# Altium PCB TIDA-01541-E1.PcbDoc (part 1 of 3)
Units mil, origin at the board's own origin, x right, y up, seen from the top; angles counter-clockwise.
Board outline 6299.21 x 6141.73 mil, 4 copper layers (Top Layer, GND, PWR, Bottom Layer), stack 79.834 mil thick; 369 components, 173 nets, 884 pads, 265 vias.
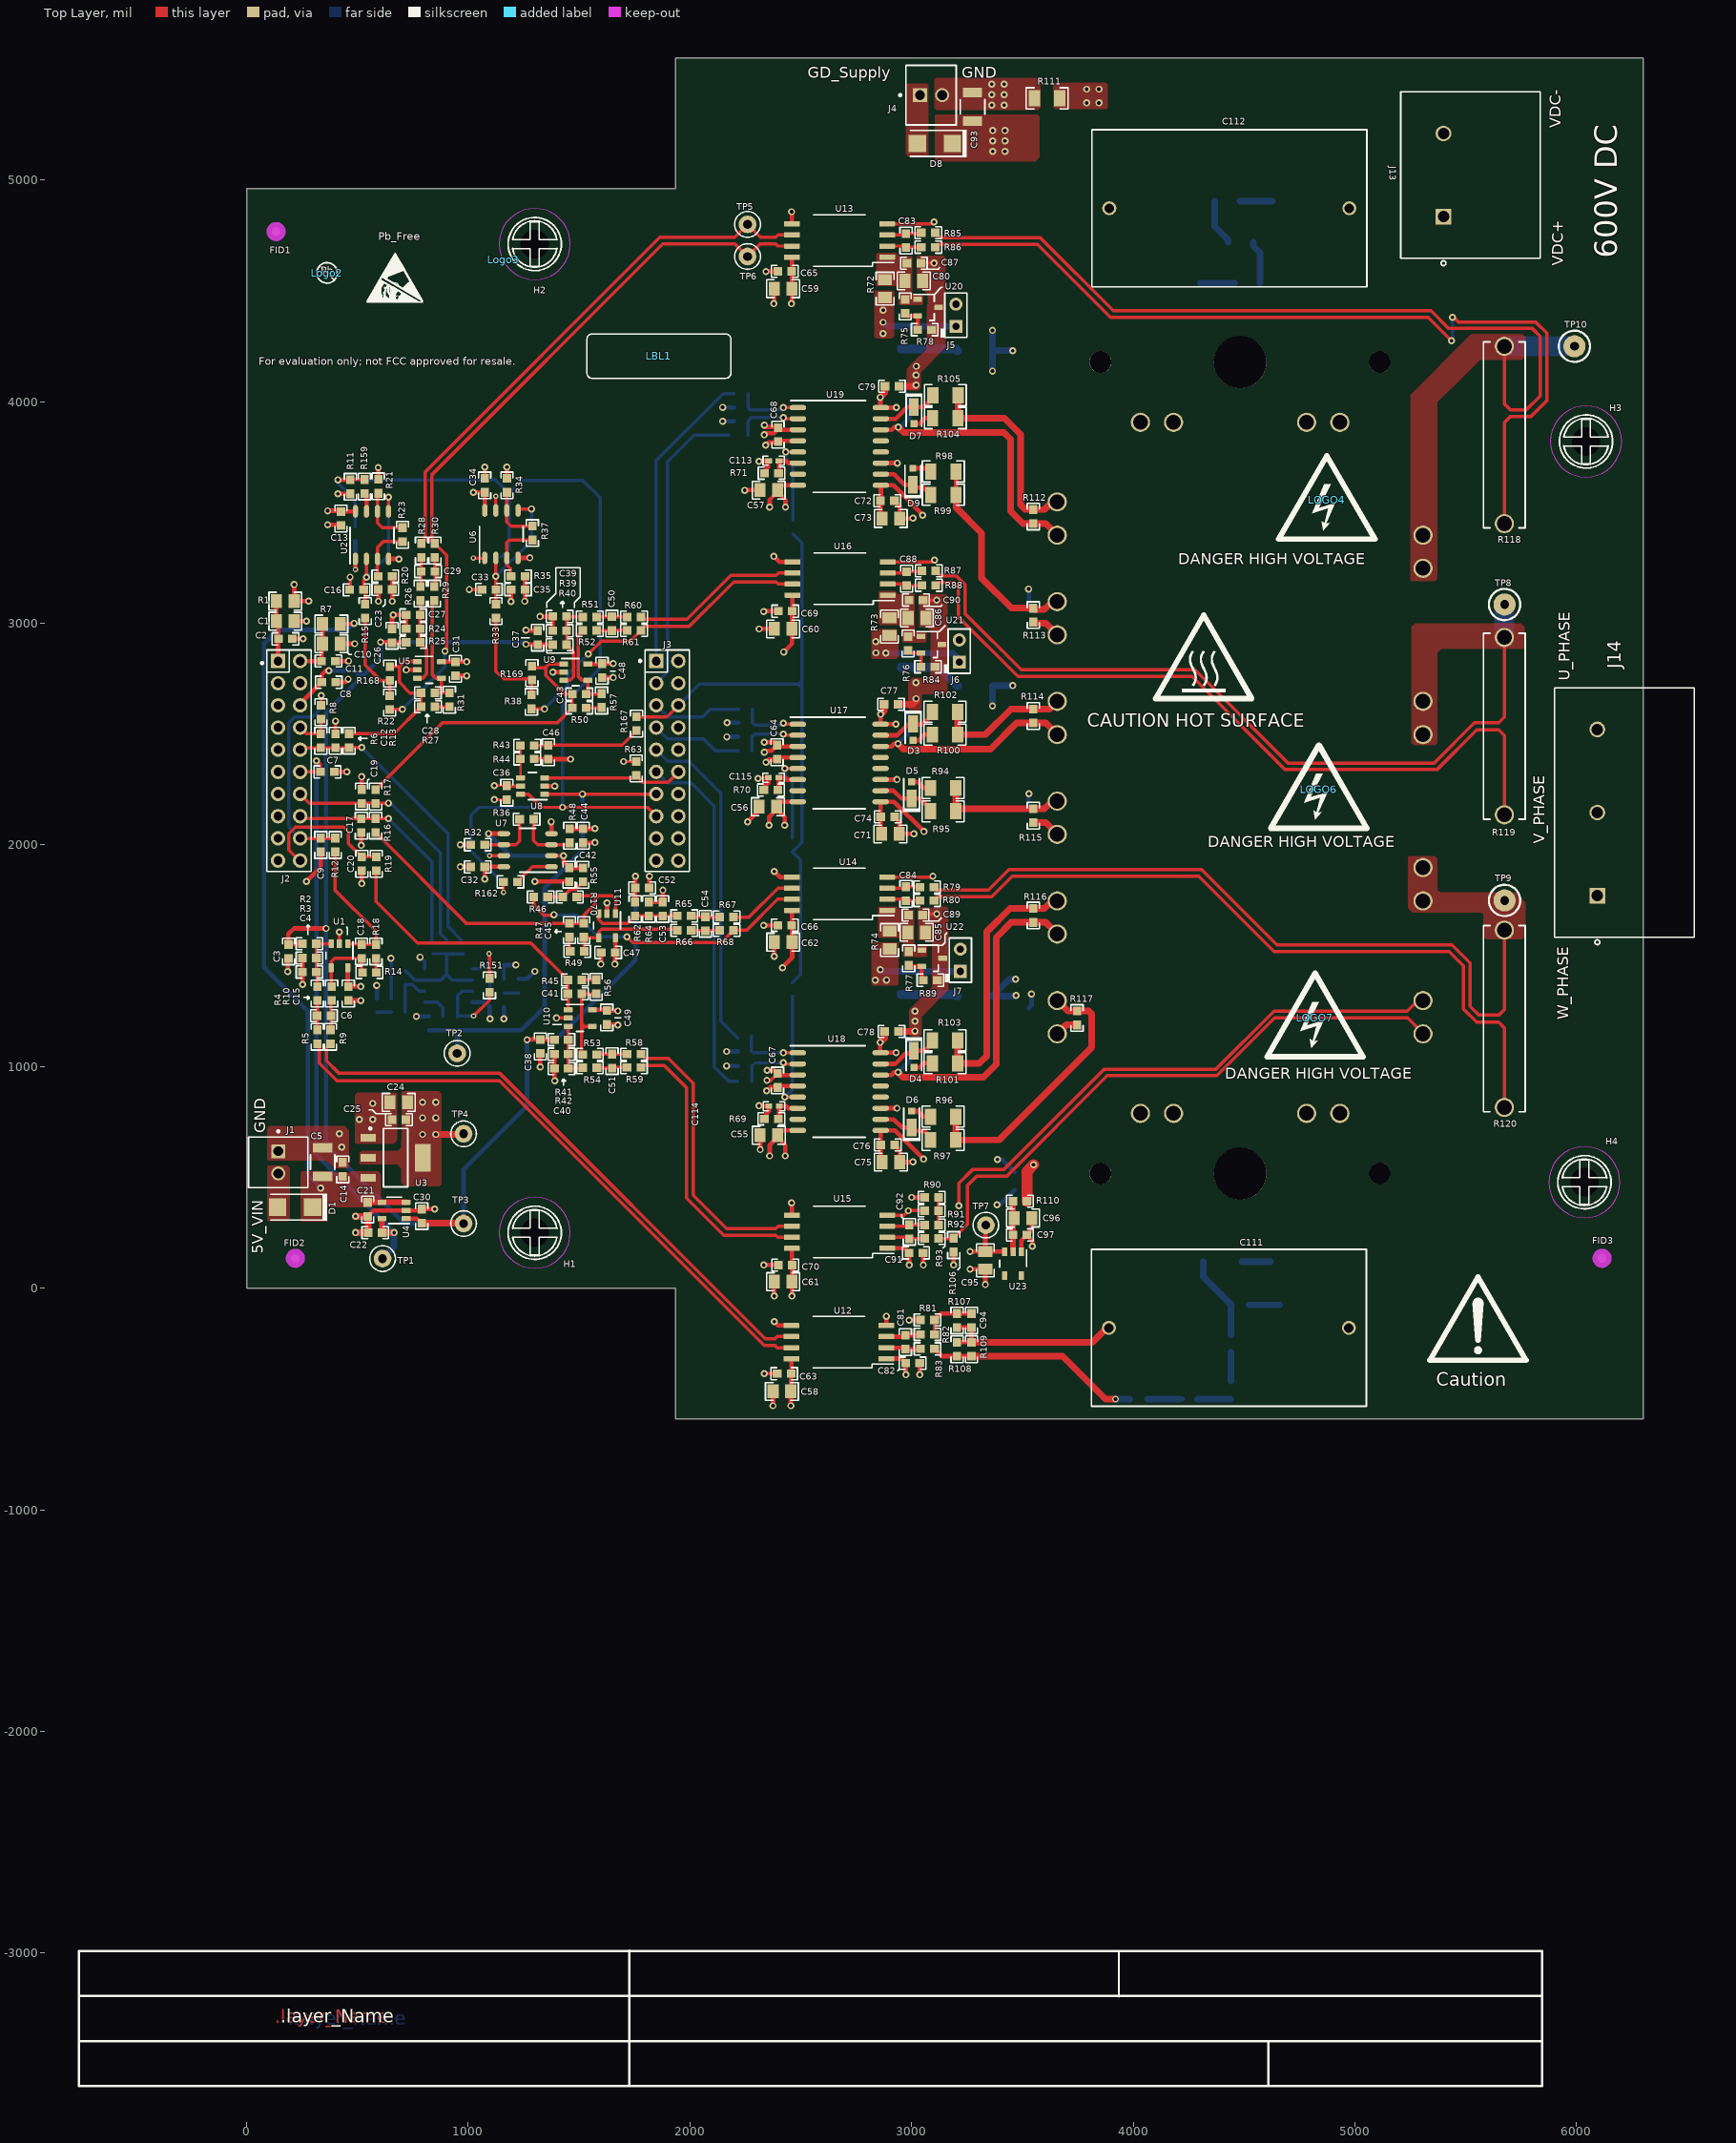
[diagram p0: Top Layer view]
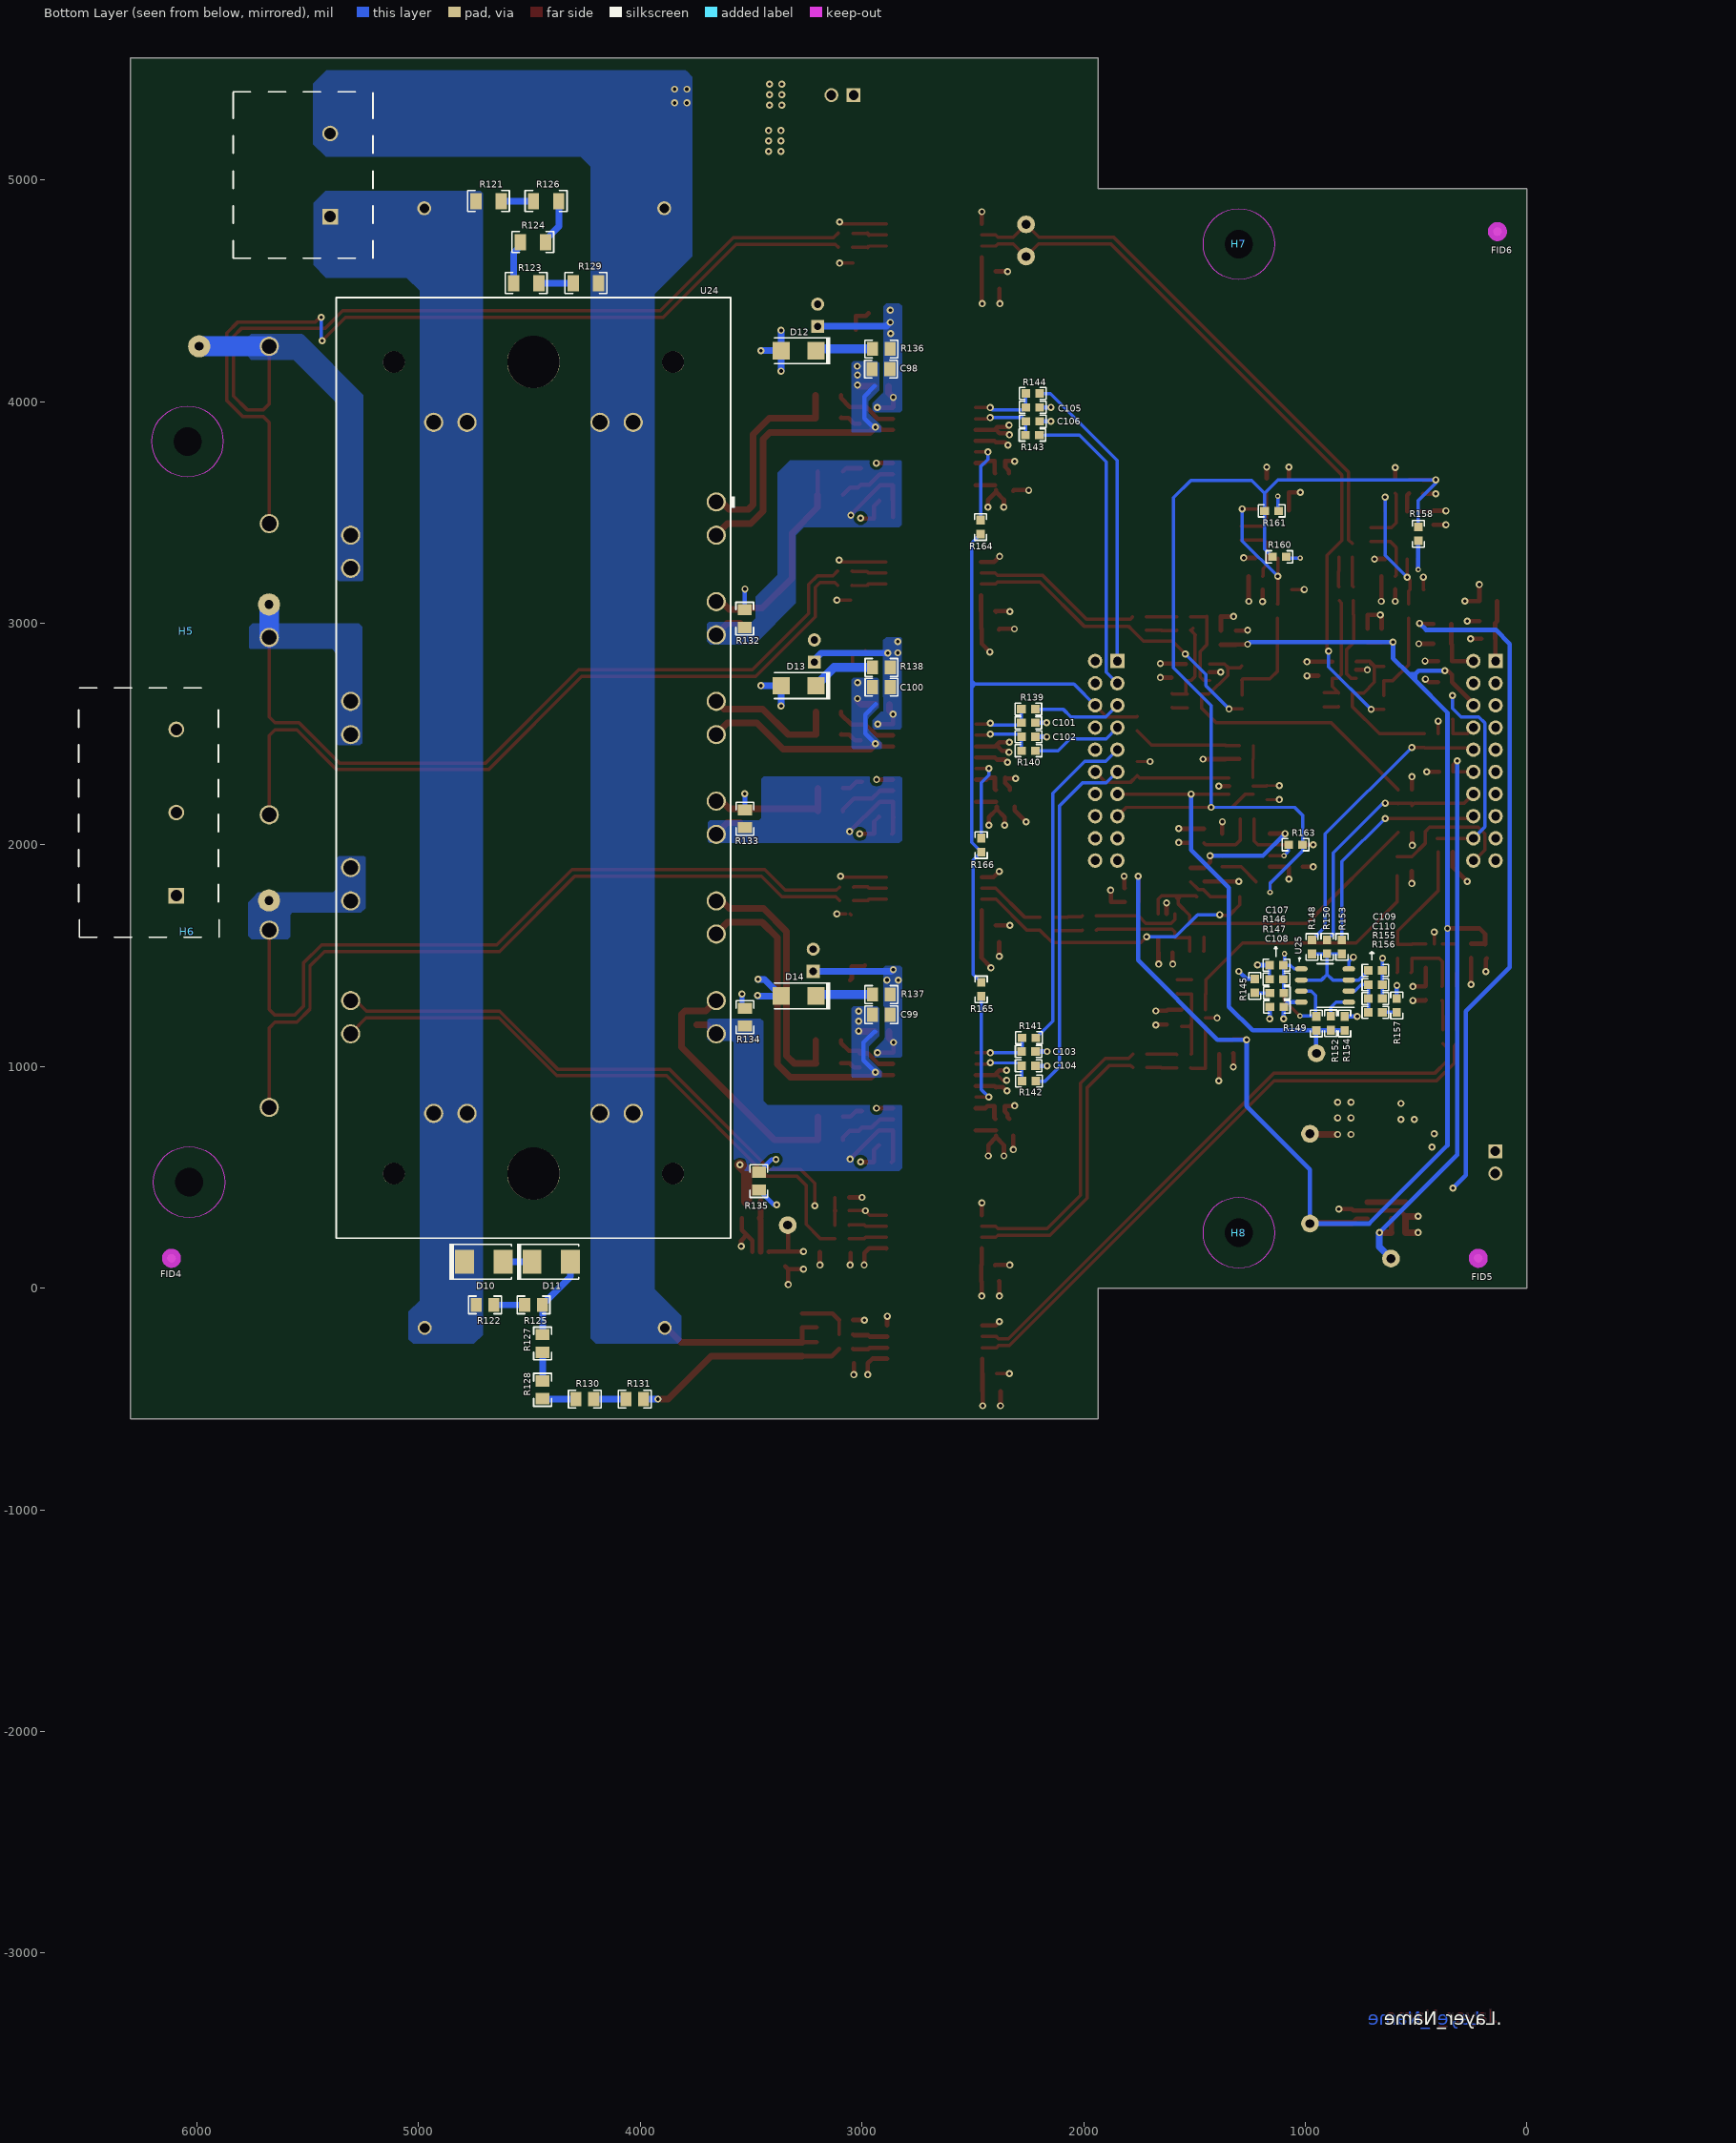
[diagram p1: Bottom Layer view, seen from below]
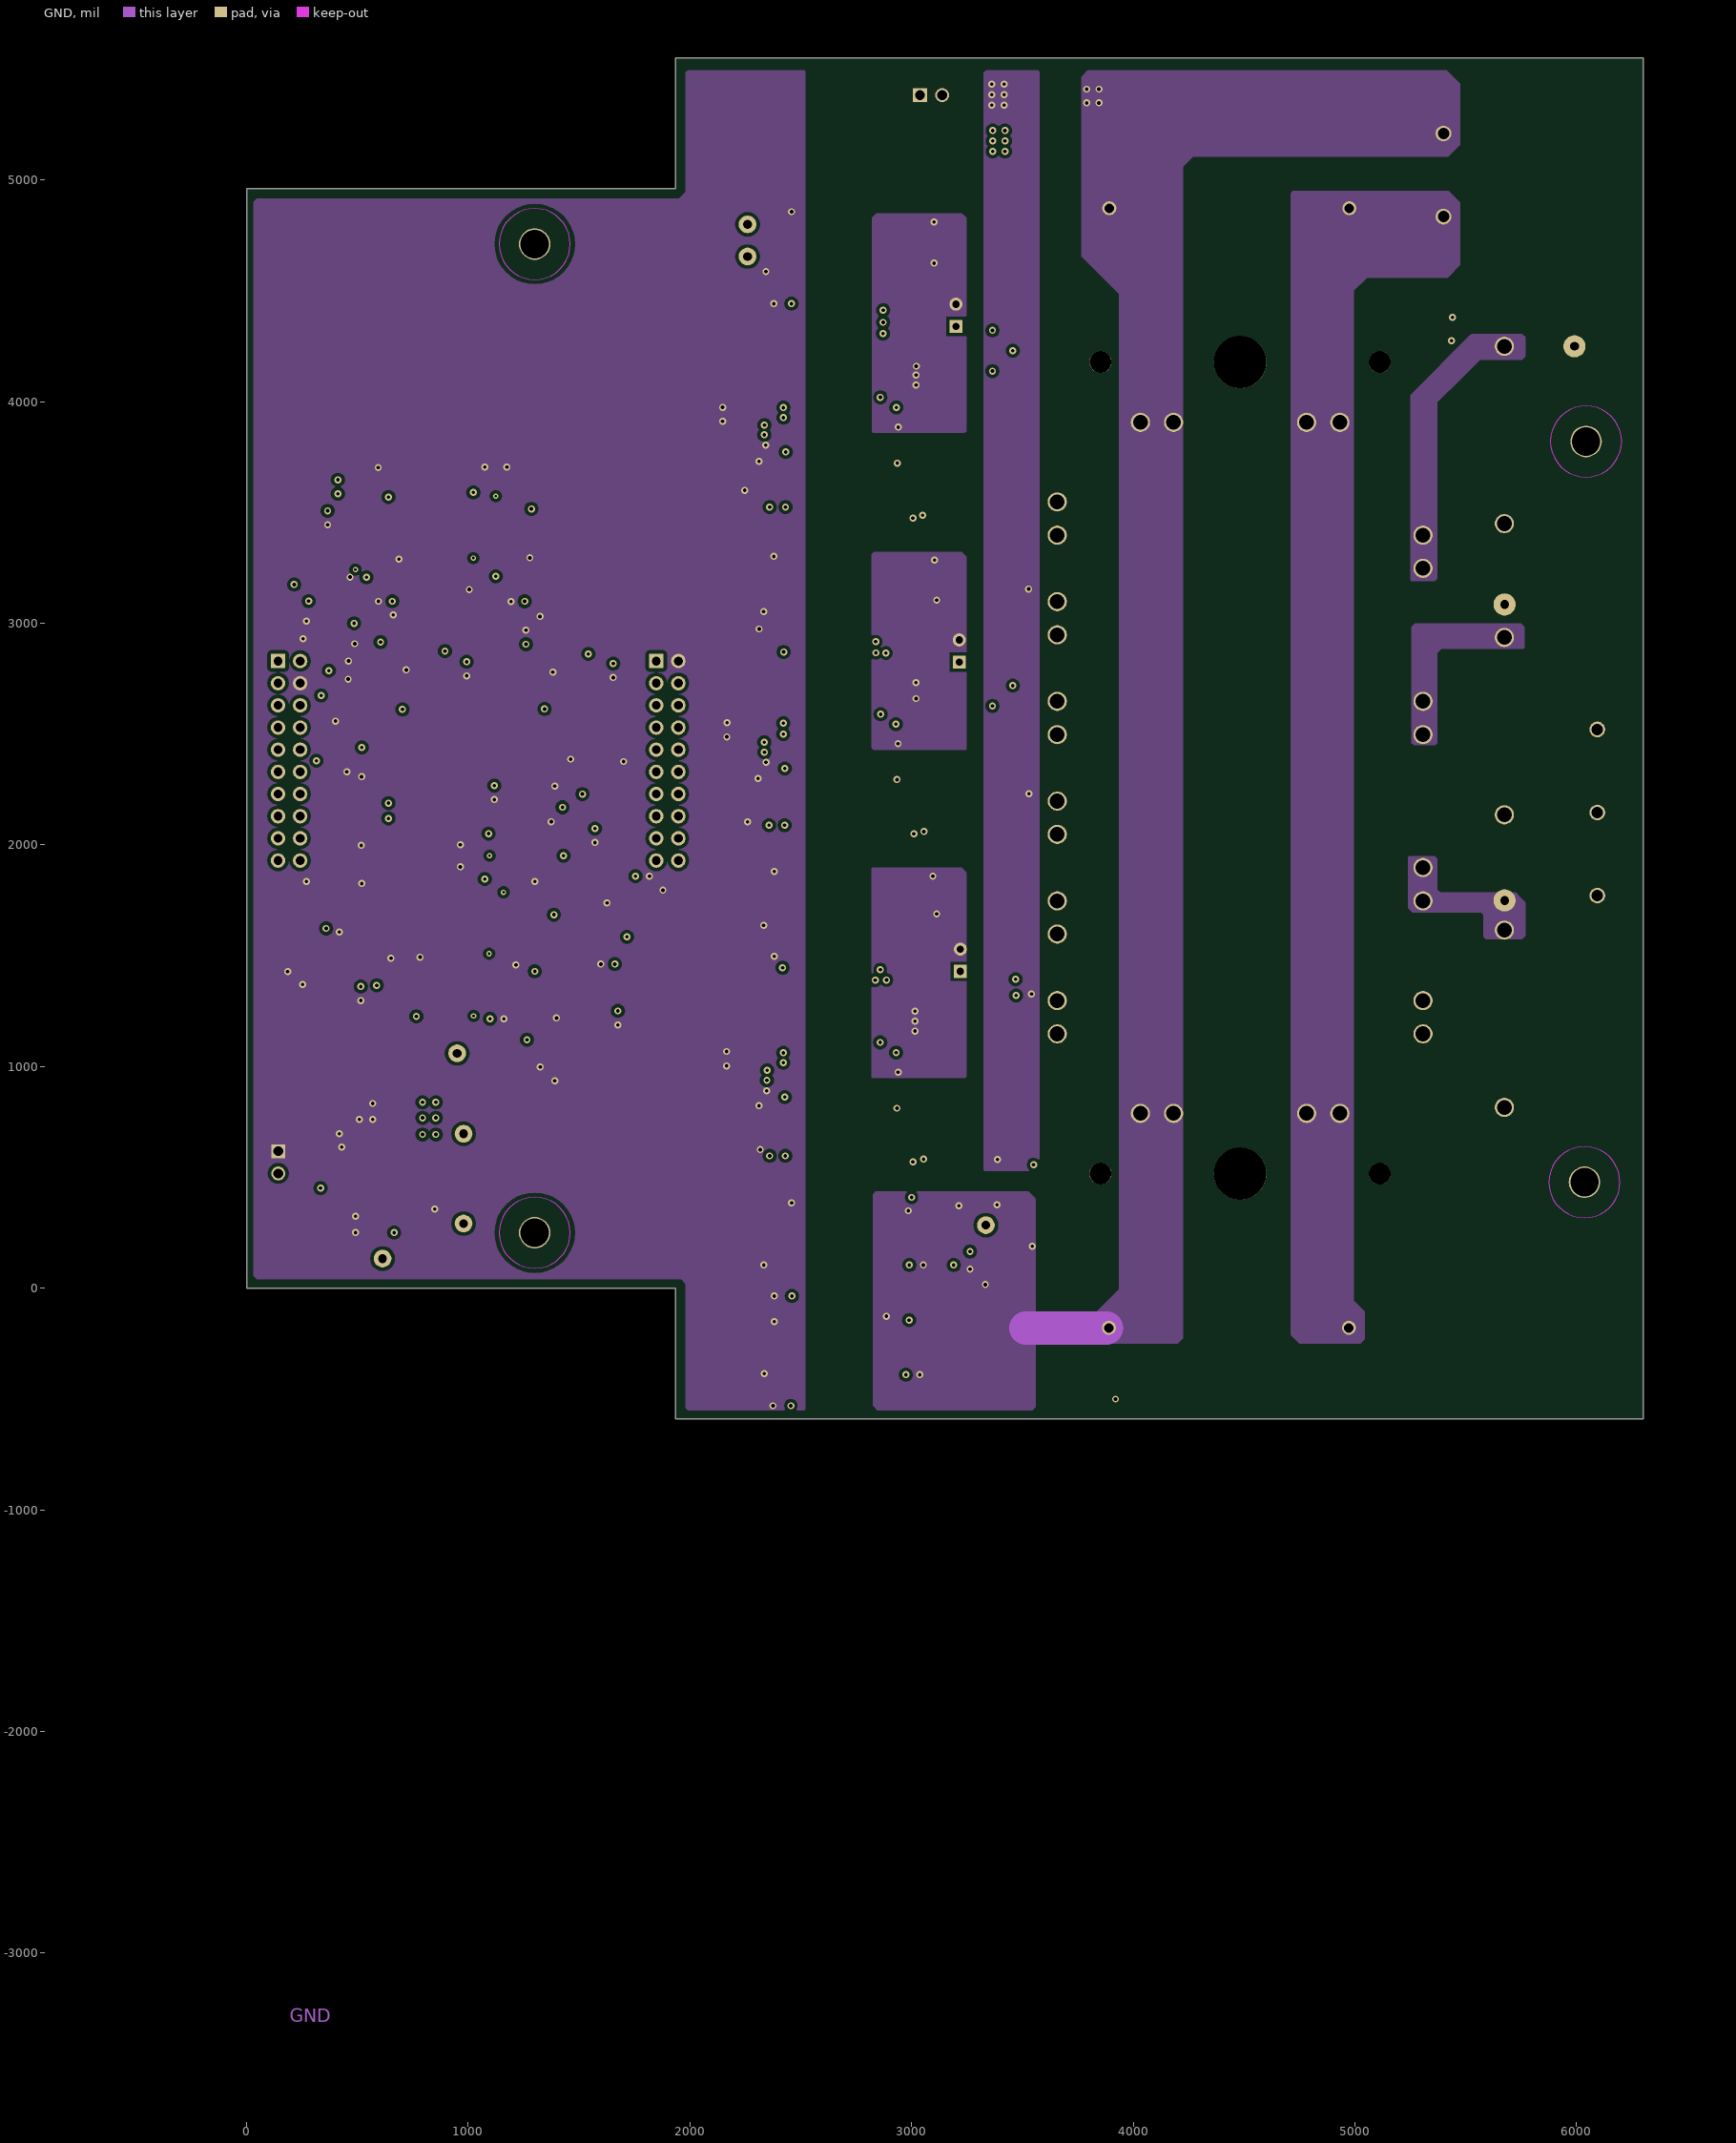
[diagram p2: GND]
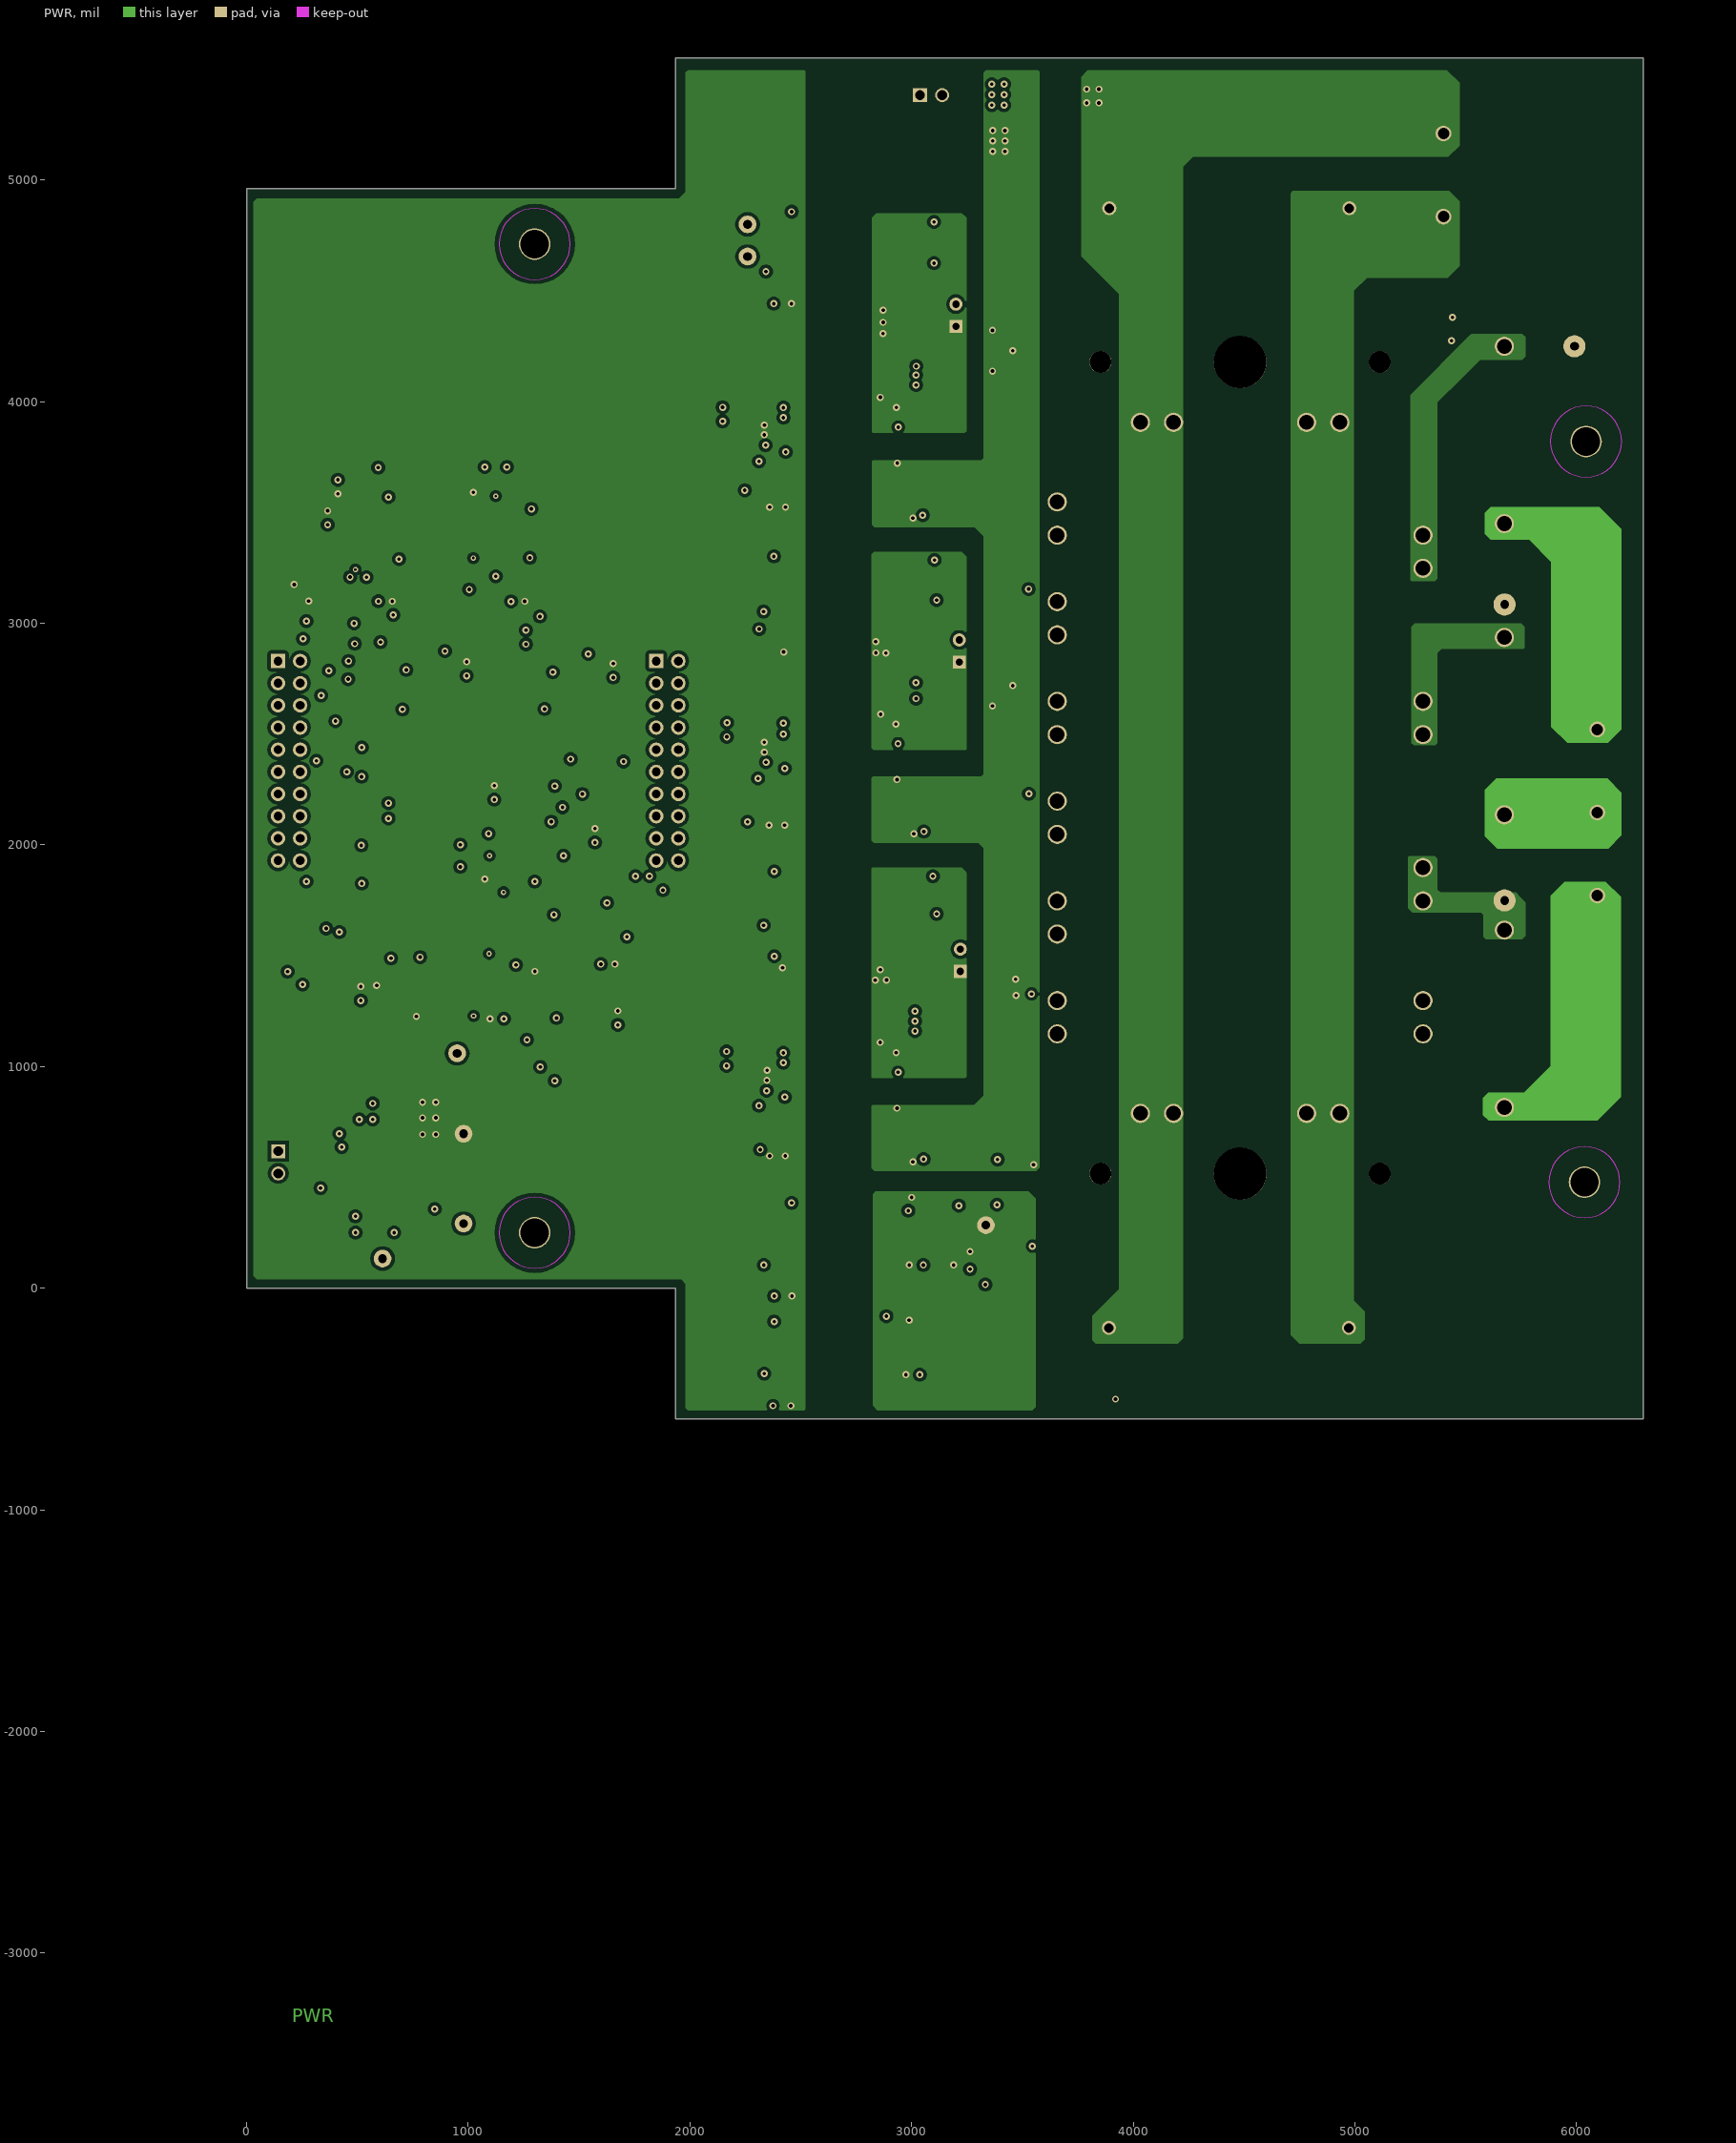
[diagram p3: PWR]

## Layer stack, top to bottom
Top Solder: solder mask 0.4, Solder Resist, Dk 3.5
Top Layer: signal copper 1.4
Dielectric1: core 59.2, FR-4, Dk 4.8
GND: signal copper 1.417
Dielectric 2: prepreg 5, Dk 4.2
PWR: signal copper 1.417
Dielectric 3: core 10, Dk 4.2
Bottom Layer: signal copper 1.4
Bottom Solder: solder mask 0.4, Solder Resist, Dk 3.5

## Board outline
0,0 0,4960.63 1934.73,4960.63 1934.73,5551.18 6299.21,5551.18 6299.21,-590.55 1934.73,-590.55 1934.73,0

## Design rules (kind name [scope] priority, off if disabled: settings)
AcuteAngle [All] p1: minimum=4.50000000000000E+0001 checktracksonly=FALSE
AssemblyTestPointUsage [All] p1: valid=2
Clearance Clearance_Wtop [InNet('W_TOP_REF') vs InNet('W_PHASE')] p1: gap=15
Clearance Clearance_Vtop [InNet('V_TOP_REF') vs InNet('V_PHASE')] p2: gap=15
Clearance Clearance_utop [InNet('U_TOP_REF') vs InNet('U_PHASE')] p3: gap=15
Clearance Clearance_MTG_COPPER [InPadClass('MTG') vs InPolygon] p4: gap=40
Clearance Clearance_Boardedge_poly [OnCopper and InPolygon vs IsKeepOut] p5: gap=20
Clearance "Shape to Shape" [InPolygon vs InPolygon] p6: gap=20
Clearance "shape to all" [InPolygon] p7: gap=15
Clearance "Clearance_via_thr pin" [IsVia vs IsThruPin] p8: gap=8
Clearance "SMD to Via" [IsSMTPin vs IsVia] p9: gap=8
Clearance [All] p10: gap=8
DiffPairsRouting DiffPair_DiffPairsRouting [InDifferentialPair ('kan')] p1: maxlimit=10 minlimit=10 mostfreqgap=10 toplayer_minwidth=15 toplayer_maxwidth=15 toplayer_prefwidth=15 midlayer1_minwidth=15 midlayer1_maxwidth=15 midlayer1_prefwidth=15 midlayer2_minwidth=15 midlayer2_maxwidth=15 midlayer2_prefwidth=15 bottomlayer_minwidth=15 bottomlayer_maxwidth=15 bottomlayer_prefwidth=15 maxuncoupledlength=500
DiffPairsRouting DiffPair_DiffPairsRouting_1 [InDifferentialPair ('kan')] p2: maxlimit=10 minlimit=10 mostfreqgap=10 toplayer_minwidth=15 toplayer_maxwidth=15 toplayer_prefwidth=15 midlayer1_minwidth=15 midlayer1_maxwidth=15 midlayer1_prefwidth=15 midlayer2_minwidth=15 midlayer2_maxwidth=15 midlayer2_prefwidth=15 bottomlayer_minwidth=15 bottomlayer_maxwidth=15 bottomlayer_prefwidth=15 maxuncoupledlength=500
DiffPairsRouting [All] p3: maxlimit=100 minlimit=10 mostfreqgap=10 toplayer_minwidth=15 toplayer_maxwidth=15 toplayer_prefwidth=15 midlayer1_minwidth=15 midlayer1_maxwidth=15 midlayer1_prefwidth=15 midlayer2_minwidth=15 midlayer2_maxwidth=15 midlayer2_prefwidth=15 bottomlayer_minwidth=15 bottomlayer_maxwidth=15 bottomlayer_prefwidth=15 maxuncoupledlength=1000
FabricationTestPointUsage TestPointUsage [All] p1: valid=2 allowmultiple=FALSE
FabricationTestpoint Testpoint [All] p1: side=3 testpointundercomponent=TRUE minsize=40 maxsize=100 preferedsize=60 minholesize=0 maxholesize=40 preferedholesize=32 testpointgrid=1 allowsidetop=TRUE allowsidebottom=TRUE usegrid=TRUE gridtolerance=0.01
FanoutControl Fanout_LCC [IsLCC] p1: bgadir=Out bgaviamode=Centered fanoutstyle=Auto fanoutdirection=Alternating viagrid=1 // Fanout_LCC (Default Rule)
FanoutControl Fanout_BGA [IsBGA] p2: bgadir=Out bgaviamode=Centered fanoutstyle=Auto fanoutdirection=Alternating viagrid=1 // Fanout_BGA (Default Rule)
FanoutControl Fanout_Default [All] p4: bgadir=Out bgaviamode=Centered fanoutstyle=Auto fanoutdirection=Alternating viagrid=1 // Fanout_Default (Default Rule)
FanoutControl Fanout_Small [(CompPinCount < 5)] p5: bgadir=Out bgaviamode=Centered fanoutstyle=Auto fanoutdirection=OutThenIn viagrid=1 // Fanout_Small (Default Rule)
HoleSize [All] p1: absolutevalues=TRUE maxlimit=1500 minlimit=7 maxpercent=80.000 minpercent=20.000
MatchedLengths DiffPair_MatchedLengths [InDifferentialPair ('kan')] p1: tolerance=1000 checknetsindiffpair=TRUE checkdiffpairvsdiffpair=FALSE checkxsignals=FALSE checkothers=FALSE
MatchedLengths DiffPair_MatchedLengths_1 [InDifferentialPair ('kan')] p2: tolerance=1000 checknetsindiffpair=TRUE checkdiffpairvsdiffpair=FALSE checkxsignals=FALSE checkothers=FALSE
MinimumAnnularRing [All] p1: minimumring=5
MinimumAnnularRing MinimumAnnularRing_ThermalPadVias [IsVia and InAnyComponent] p2: minimumring=5.91
MinimumSolderMaskSliver MinimumSolderMaskSliver_Logo [InComponentClass('Logo') vs InComponentClass('Logo')] p1: minsoldermaskwidth=0.7
MinimumSolderMaskSliver [All] p2: minsoldermaskwidth=3.94
PlaneClearance [All] p1: clearance=15
PlaneConnect [All] p1: planeconnectstyle=Direct reliefexpansion=10 reliefentries=4 reliefconductorwidth=10 reliefairgap=10
PolygonConnect [All] p1: connectstyle=Direct reliefconductorwidth=10 reliefentries=4 polygonreliefangle="90 Angle" airgapwidth=10
RoutingVias RoutingVias_power [InNetClass('POWER')] p1: holewidth=16 width=32 viastyle="Through Hole" minholewidth=7.87 minwidth=19.68 maxholewidth=16 maxwidth=32
RoutingVias ThermalPadVias [IsVia and InAnyComponent] p2: holewidth=8 width=20 viastyle="Through Hole" minholewidth=7.87 minwidth=19 maxholewidth=12 maxwidth=24
RoutingVias [All] p3: holewidth=12 width=24 viastyle="Through Hole" minholewidth=12 minwidth=24 maxholewidth=16 maxwidth=32
SMDToCorner [All] p1: distance=30000
SilkToSilkClearance [All] p1: silktosilkclearance=5
SilkToSolderMaskClearance SilkscreenOverComponentPads [IsPad] p1: minsilkscreentomaskgap=5 clearancetoexposedcopper=TRUE
SolderMaskExpansion [All] p1: expansion=3
Width Width_power [InNetClass('pwr')] p1: maxlimit=200 minlimit=8 preferedwidth=20
Width [All] p2: maxlimit=250 minlimit=12 preferedwidth=20 checkconnectedcopper=TRUE
16 further rules are at their usual default settings.

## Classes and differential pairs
component class Label: LBL1
component class AssemblyNote: ZZ1 ZZ2 ZZ3 ZZ4
component class Header: J2 J3 J5 J6 J7
pad class MTG: H1-1 H2-1 H3-1 H4-1 H5-0 H6-0 H7-0 H8-0
component class FiducialMark: FID1 FID2 FID3 FID4 FID5 FID6
component class TIDA-01541-E1_EVM_Hardware: Caution "CAUTION HOT SURFACE" FID1 FID2 FID3 FID4 FID5 FID6 H1 H2 H3 H4 H5 H6 H7 H8 LBL1 Logo2 Logo3 LOGO4 LOGO6 LOGO7 Pb_Free ZZ1 ZZ2 ZZ3 ZZ4
component class "TIDA-01541-E1_Current sense": C12 C13 C16 C17 C19 C23 C26 C27 C28 C29 C31 C32 C33 C34 C35 C37 C39 C42 C43 C44 C45 C47 C48 C50 C52 C53 C54 C59 C60 C62 C65 C66 C69 C80 C83 C84 C85 C86 C87 C88 C89 C90 R11 R13 R15 R16 R17 R20 R21 R22 R23 R24 R25 R26 R27 R28 R29 R30 R31 R32 R33 R34 R35 R36 R37 R38 R39 R40 R46 R47 R48 R49 R50 R51 R52 R55 R57 R60 R61 R62 R64 R65 R66 R67 R68 R72 R73 R74 R75 R76 R77 R78 R79 R80 R84 R85 R86 R87 R88 R89 R158 R159 R160 R161 R162 R163 R168 R169 R170 TP5 TP6 U2 U5 U6 U7 U9 U11 U13 U14 U16 U20 U21 U22
component class "TIDA-01541-E1_DC BUS and TEMP Sense": C3 C4 C6 C9 C15 C18 C20 C38 C40 C41 C49 C51 C58 C61 C63 C70 C81 C82 C91 C92 C94 C95 C96 C97 D10 D11 R2 R3 R4 R5 R9 R10 R12 R14 R18 R19 R41 R42 R45 R53 R54 R56 R58 R59 R81 R82 R83 R90 R91 R92 R93 R107 R108 R109 R110 R122 R125 R127 R128 R130 R131 TP7 U1 U10 U12 U15 U23
component class "TIDA-01541-E1_Gate driver and Module": C36 C46 C55 C56 C57 C64 C67 C68 C71 C72 C73 C74 C75 C76 C77 C78 C79 C93 C98 C99 C100 C111 C112 C113 C114 C115 D3 D4 D5 D6 D7 D8 D9 D12 D13 D14 J4 J5 J6 J7 J13 J14 R43 R44 R69 R70 R71 R94 R95 R96 R97 R98 R99 R100 R101 R102 R103 R104 R105 R106 R111 R112 R113 R114 R115 R116 R117 R118 R119 R120 R121 R123 R124 R126 R129 R132 R133 R134 R135 R136 R137 R138 R164 R165 R166 TP8 TP9 TP10 U8 U17 U18 U19 U24
component class "TIDA-01541-E1_MCU Interface": C1 C2 C5 C7 C8 C10 C11 C14 C21 C22 C24 C25 C30 C101 C102 C103 C104 C105 C106 C107 C108 C109 C110 D1 J1 J2 J3 R1 R6 R7 R8 R63 R139 R140 R141 R142 R143 R144 R145 R146 R147 R148 R149 R150 R151 R152 R153 R154 R155 R156 R157 R167 TP1 TP2 TP3 TP4 U3 U4 U25

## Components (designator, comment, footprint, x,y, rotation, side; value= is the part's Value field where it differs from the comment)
C1 "C2012X5R1H475K125AB" 0805_HV 174.73,3009.45 r180 top
C2 "GRM188R71H104KA93D" 0603 174.73,2929.45 r180 top
C3 "GRM188R71H104KA93D" 0603 188.73,1519.4 r90 top
C4 "885012206040" 0603 283.73,1426.4 r180 top
C5 "C3225X5R1H106K250AB" 1210_280 342.73,568.45 r90 top
C6 "885012206040" 0603 348.73,1229.4 r180 top
C7 "GRM188R71H104KA93D" 0603 364.73,2329.45 r0 top
C8 "GRM188R71H104KA93D" 0603 370,2734 r0 top
C9 "GRM188R71H104KA93D" 0603 334.73,1999.45 r270 top
C10 "C2012X5R1H475K125AB" 0805_HV 381.73,2907.45 r0 top
C11 "GRM188R71H104KA93D" 0603 369.73,2829.45 r0 top
C12 "06031C152JAT2A" 0603 400.73,2469.45 r90 top
C13 "GRM188R71H104KA93D" 0603 425.51,3472.34 r270 top
C14 "GRM188R71H104KA93D" 0603 433.73,536.45 r90 top
C15 "GRM188R71H104KA93D" 0603 458.73,1329.4 r270 top
C16 "885012206040" 0603 496.74,3150.95 r180 top
C17 "06031C152JAT2A" 0603 517.73,2086.45 r270 top
C18 "885012206040" 0603 518.73,1519.4 r90 top
C19 "06031C152JAT2A" 0603 518.73,2218.45 r90 top
C20 "GRM188R71H104KA93D" 0603 519.73,1914.45 r270 top
C21 "GRM188R71H104KA93D" 0603 546.38,355.61 r270 top
C22 "GRM188R71H104KA93D" 0603 580.38,250.61 r180 top
C23 "GRM188R71H104KA93D" 0603 625.51,3152.34 r180 top
C24 "CL21A226MAQNNNE" 0805_HV 685.73,838.45 r180 top
C25 "GRM188R71H104KA93D" 0603 686.73,760.45 r180 top
C26 "GRM188R71H104KA93D" 0603 655.73,2943.45 r270 top
C27 "06035A181JAT2A" 0603 750.73,3037.45 r180 top
C28 "06035A181JAT2A" 0603 817.73,2685.45 r180 top
C29 "06035A181JAT2A" 0603 818.61,3233.45 r180 top
C30 "GRM188R71H104KA93D" 0603 790.38,325.61 r90 top
C31 "GRM188R71H104KA93D" 0603 941.73,2794.45 r270 top
C32 "GRM188R71H104KA93D" 0603 1042.88,1900.91 r180 top
C33 "885012206040" 0603 1092.82,3152.19 r180 top
C34 "GRM188R71H104KA93D" 0603 1074.21,3621.76 r90 top
C35 "GRM188R71H104KA93D" 0603 1224.21,3151.76 r180 top
C36 "GRM188R71H104KA93D" 0603 1173.57,2235.73 r270 top
C37 "GRM188R71H104KA93D" 0603 1313.06,2935.12 r270 top
C38 "GRM188R71H104KA93D" 0603 1324.73,1090.91 r90 top
C39 "06035A181JAT2A" 0603 1412.54,3030.62 r180 top
C40 "885012206040" 0603 1419.73,990.91 r180 top
C41 "885012206040" 0603 1480.53,1327.91 r180 top
C42 "885012206040" 0603 1454.96,1865.91 r270 top
C43 "06035A181JAT2A" 0603 1500.26,2680.32 r180 top
C44 "GRM188R71H104KA93D" 0603 1517.88,2040.91 r270 top
C45 "06035A181JAT2A" 0603 1520.96,1614.91 r90 top
C46 "885012206040" 0603 1360.73,2418.23 r270 top
C47 "GRM188R71H104KA93D" 0603 1630.96,1514.91 r180 top
C48 "GRM188R71H104KA93D" 0603 1603.26,2786.32 r270 top
C49 "GRM188R71H104KA93D" 0603 1624.73,1220.91 r270 top
C50 "06035A181JAT2A" 0603 1647.75,2997.99 r90 top
C51 "885012206040" 0603 1648.28,1024.45 r270 top
C52 "GRM188R71H104KA93D" 0603 1784.41,1805.91 r180 top
C53 "06035A181JAT2A" 0603 1876.41,1710.91 r90 top
C54 "06035A181JAT2A" 0603 2069.73,1644.45 r90 top
C55 "C2012X5R1H475K125AB" 0805_HV 2355,690 r180 top
C56 "C2012X5R1H475K125AB" 0805_HV 2351.73,2172.45 r180 top
C57 "C2012X5R1H475K125AB" 0805_HV 2354.99,3600.45 r180 top
C58 "C2012X5R1H475K125AB" 0805_HV 2414.73,-465.55 r0 top
C59 "C2012X5R1H475K125AB" 0805_HV 2419.73,4509.45 r0 top
C60 "C2012X5R1H475K125AB" 0805_HV 2419.73,2974.45 r0 top
C61 "C2012X5R1H475K125AB" 0805_HV 2419.73,29.45 r0 top
C62 "C2012X5R1H475K125AB" 0805_HV 2420.73,1561.45 r0 top
C63 "GRM188R71H104KA93D" 0603 2424.73,-385.55 r0 top
C64 "GRM188R71H104KA93D" 0603 2392.73,2418.45 r270 top
C65 "GRM188R71H104KA93D" 0603 2427.73,4587.45 r0 top
C66 "GRM188R71H104KA93D" 0603 2427.73,1637.45 r0 top
C67 "GRM188R71H104KA93D" 0603 2395.12,936.86 r270 top
C68 "GRM188R71H104KA93D" 0603 2397,3851 r270 top
C69 "GRM188R71H104KA93D" 0603 2429.73,3054.45 r0 top
C70 "GRM188R71H104KA93D" 0603 2429.73,104.45 r0 top
C71 "C2012X5R1H475K125AB" 0805_HV 2904.73,2049.45 r0 top
C72 "GRM188R71H104KA93D" 0603 2890.73,3552.45 r0 top
C73 "C2012X5R1H475K125AB" 0805_HV 2905.73,3472.45 r0 top
C74 "GRM188R71H104KA93D" 0603 2891.73,2126.45 r0 top
C75 "C2012X5R1H475K125AB" 0805_HV 2905.86,568.86 r0 top
C76 "GRM188R71H104KA93D" 0603 2891.86,645.86 r0 top
C77 "C1608X5R1H474K080AB" 0603 2906.73,2634.45 r180 top
C78 "C1608X5R1H474K080AB" 0603 2908.86,1157.86 r180 top
C79 "C1608X5R1H474K080AB" 0603 2910.73,4069.45 r180 top
C80 "C2012X5R1H475K125AB" 0805_HV 3009.73,4544.45 r180 top
C81 "885012206040" 0603 2971.73,-243.55 r90 top
C82 "GRM188R71H104KA93D" 0603 3004.73,-338.55 r180 top
C83 "885012206040" 0603 2974.73,4726.58 r90 top
C84 "885012206040" 0603 2974.73,1779.45 r90 top
C85 "C2012X5R1H475K125AB" 0805_HV 3022.73,1605.45 r180 top
C86 "C2012X5R1H475K125AB" 0805_HV 3023.73,3023.45 r180 top
C87 "GRM188R71H104KA93D" 0603 3009.73,4624.45 r180 top
C88 "885012206040" 0603 2977.08,3201.32 r90 top
C89 "GRM188R71H104KA93D" 0603 3017.73,1683.45 r180 top
C90 "GRM188R71H104KA93D" 0603 3019.73,3104.45 r180 top
C91 "GRM188R71H104KA93D" 0603 3019.73,159.45 r180 top
C92 "885012206040" 0603 2989.73,254.45 r90 top
C93 "C3225X5R1H106K250AB" 1210_280 3274.73,5329.45 r90 top
C94 "GRM188R71H104KA93D" 0603 3269.73,-145.55 r90 top
C95 "C2012X5R1H475K125AB" 0805_HV 3332.33,125.32 r270 top
C96 "C2012X5R1H475K125AB" 0805_HV 3502.33,316.32 r0 top
C97 "GRM188R71H104KA93D" 0603 3488.33,240.32 r0 top
C98 "C2012X7R1H225K125AC" 0805_HV 2913.73,4146.45 r180 bottom
C99 "C2012X7R1H225K125AC" 0805_HV 2911.86,1233.86 r180 bottom
C100 "C2012X7R1H225K125AC" 0805_HV 2911.73,2711.45 r180 bottom
C101 "GRM1885C1H100JA01D" 0603 2249.73,2550.99 r180 bottom
C102 "GRM1885C1H100JA01D" 0603 2248.73,2487.65 r180 bottom
C103 "GRM1885C1H100JA01D" 0603 2247.73,1067.99 r180 bottom
C104 "GRM1885C1H100JA01D" 0603 2247.73,1002.99 r180 bottom
C105 "GRM1885C1H100JA01D" 0603 2229.73,3973.99 r180 bottom
C106 "GRM1885C1H100JA01D" 0603 2229.73,3910.99 r180 bottom
C107 "GRM188R71H821KA01D" 0603 1129.73,1456.99 r180 bottom
C108 "GRM188R71H104KA93D" 0603 1128.73,1268.99 r180 bottom
C109 "GRM188R71H821KA01D" 0603 683.76,1433.45 r0 bottom
C110 "GRM188R71H821KA01D" 0603 683.76,1369.45 r0 bottom
C111 "B32774D1305K000" B32774_3150x1800x2750 4431,-179 r180 top
C112 "B32774D1305K000" B32774_3150x1800x2750 4433,4872 r180 top
C113 "GRM155R71C222KA01D" 0402 2378,3733 r180 top
C114 "GRM155R71C222KA01D" 0402 2379,821 r180 top
C115 "GRM155R71C222KA01D" 0402 2377,2303 r180 top
Caution "CAUTION.  READ USER GUIDE BEFORE USE" IEC_Caution_Medium 5555,-143 r0 top
"CAUTION HOT SURFACE" "CAUTION HOT SURFACE" IEC_HotSurface_Medium 4317,2848 r0 top
D1 "B1100-13-F" SMA 218.73,365.45 r180 top
D3 "MSS2P3-M3/89A" MicroSMP 3006.23,2520.45 r270 top
D4 "MSS2P3-M3/89A" MicroSMP 3010,1045 r270 top
D5 "MSS2P3-M3/89A" MicroSMP 3000,2235 r90 top
D6 "MSS2P3-M3/89A" MicroSMP 3000,750 r90 top
D7 "MSS2P3-M3/89A" MicroSMP 3010,3950 r270 top
D8 "B1100-13-F" SMA 3104.73,5164.45 r180 top
D9 "MSS2P3-M3/89A" MicroSMP 3005,3650 r90 top
D10 "1SMB5956BT3G" SMB 4705.74,119.45 r180 bottom
D11 "1SMB5956BT3G" SMB 4401.74,119.45 r180 bottom
D12 "BYG23T-M3/TR" SMA 3285.73,4229.45 r0 bottom
D13 "BYG23T-M3/TR" SMA 3285.73,2718.45 r0 bottom
D14 "BYG23T-M3/TR" SMA 3285.73,1318.45 r0 bottom
FID1 "Fiducial" Fiducial10-20 133.32,4767 r270 top
FID2 "Fiducial" Fiducial10-20 220,135 r270 top
FID3 "Fiducial" Fiducial10-20 6114.73,135 r270 top
FID4 "Fiducial" Fiducial10-20 6114.73,135 r270 bottom
FID5 "Fiducial" Fiducial10-20 220,135 r270 bottom
FID6 "Fiducial" Fiducial10-20 133.32,4767 r270 bottom
H1 "MH 3.2mm" MH3.2_H5_W6_KO8_STARHEAD 1299.63,250 r180 top
H2 "MH 3.2mm" MH3.2_H5_W6_KO8_STARHEAD 1299.63,4710.63 r180 top
H3 "MH 3.2mm" MH3.2_H5_W6_KO8_STARHEAD 6042,3820 r180 top
H4 "MH 3.2mm" MH3.2_H5_W6_KO8_STARHEAD 6035,478 r180 top
H5 "1902C" Keystone_1902C 6048.95,2964.45 r0 bottom
H6 "1902C" Keystone_1902C 6043.95,1609.45 r0 bottom
H7 "1902C" Keystone_1902C 1299.63,4710.63 r0 bottom
H8 "1902C" Keystone_1902C 1299.63,250 r0 bottom
J1 "282834-2" TEC_282834-2 142.73,567.45 r270 top
J2 "TSW-110-07-G-D" TSW-110-07-G-D 191.73,2379.45 r270 top locked
J3 "TSW-110-07-G-D" TSW-110-07-G-D 1897.73,2379.45 r270 top locked
J4 "282834-2" TEC_282834-2 3087.73,5382.45 r0 top
J5 "800-10-002-10-001000" Mill-Max_800-10-002-10-001000 3199.73,4389.45 r90 top
J6 "800-10-002-10-001000" Mill-Max_800-10-002-10-001000 3214.73,2874.45 r90 top
J7 "800-10-002-10-001000" Mill-Max_800-10-002-10-001000 3219.73,1479.45 r90 top
J13 "1902547" PHOENIX_1902547#1 5521,5022 r90 top
J14 "1904150" PHOENIX_1902547#2 6215,2146 r90 top
LBL1 "Size: 0.65\" x 0.20 \"" Label_650x200 1860,4205 r180 top
Logo2 "Pb-Free Symbol" Pb-Free_Overlay_Small 363.07,4580.5 r0 top
Logo3 "FCC disclaimer" FCC_disclaimer 1157.73,4639.45 r0 top
LOGO4 "DANGER HIGH VOLTAGE" IEC_HighVoltage_medium 4873,3555 r0 top
LOGO6 "DANGER HIGH VOLTAGE" IEC_HighVoltage_medium 4837,2250 r0 top
LOGO7 "DANGER HIGH VOLTAGE" IEC_HighVoltage_medium 4820,1220 r0 top
Pb_Free "ESD Susceptible" ESD_Overlay_Medium 669,4558 r0 top
R1 "ERJ-6GEY0R00V" 0805_HV 174.73,3099.45 r180 top
R2 "ERJ-3EKF7501V" 0603 283.73,1554.4 r0 top
R3 "RC0603FR-0715KL" 0603 283.73,1489.4 r0 top
R4 "RC0603FR-074K7L" 0603 318.73,1329.4 r90 top
R5 "RC0603FR-074K7L" 0603 318.73,1134.4 r90 top
R6 "ERJ-3GEY0R00V" 0603 334.73,2469.45 r270 top
R7 "ERJ-6GEY0R00V" 0805_HV 381.73,2996.45 r0 top
R8 "ERJ-3GEY0R00V" 0603 335.73,2598.45 r90 top
R9 "RC0603FR-074K7L" 0603 378.73,1134.4 r90 top
R10 "RC0603FR-074K7L" 0603 383.73,1329.4 r90 top
R11 "RC0603JR-0710KL" 0603 468.27,3615.55 r270 top
R12 "RC0603FR-07100RL" 0603 399.73,1999.45 r90 top
R13 "RC0603FR-07100RL" 0603 462.73,2470.45 r270 top
R14 "ERJ-3GEY0R00V" 0603 553.73,1424.4 r0 top
R15 "ERJ-3GEY0R00V" 0603 534.73,3054.45 r90 top
R16 "RC0603FR-07100RL" 0603 581.73,2087.45 r90 top
R17 "RC0603FR-07100RL" 0603 581.73,2217.45 r270 top
R18 "ERJ-3EKF7501V" 0603 583.73,1519.4 r90 top
R19 "RC0603FR-07100RL" 0603 584.73,1914.45 r90 top
R20 "RC0603FR-073KL" 0603 625.51,3212.34 r0 top
R21 "ERJ-3EKF1501V" 0603 594.09,3617.42 r270 top
R22 "ERJ-3GEY0R00V" 0603 645,2642 r90 top
R23 "RT0603BRD077K15L" 0603 703.09,3399.42 r270 top
R24 "ERJ-3EKF7501V" 0603 750.73,2975.45 r0 top
R25 "ERJ-3EKF7501V" 0603 750.73,2913.45 r0 top
R26 "RC0603FR-074K7L" 0603 783.61,3133.45 r270 top
R27 "ERJ-3EKF7501V" 0603 818.73,2623.45 r180 top
R28 "RC0603FR-074K7L" 0603 788.61,3328.45 r270 top
R29 "RC0603FR-074K7L" 0603 846.61,3133.45 r270 top
R30 "RC0603FR-074K7L" 0603 848.61,3328.45 r270 top
R31 "ERJ-3GEY0R00V" 0603 914.73,2654.45 r270 top
R32 "ERJ-3EKF1501V" 0603 1042.88,2000.91 r0 top
R33 "ERJ-3GEY0R00V" 0603 1124.73,3054.45 r90 top
R34 "ERJ-3EKF1501V" 0603 1174.21,3621.76 r270 top
R35 "RC0603FR-073KL" 0603 1224.21,3211.76 r0 top
R36 "RT0603BRD077K15L" 0603 1262.88,2115.91 r0 top
R37 "RT0603BRD077K15L" 0603 1289.21,3406.76 r270 top
R38 "ERJ-3GEY0R00V" 0603 1285,2645 r90 top
R39 "ERJ-3EKF7501V" 0603 1412.06,2966.12 r0 top
R40 "ERJ-3EKF7501V" 0603 1412.06,2903.12 r0 top
R41 "ERJ-3EKF7501V" 0603 1419.73,1120.91 r0 top
R42 "RC0603FR-0715KL" 0603 1419.73,1055.91 r0 top
R43 "ERJ-3GEY0R00V" 0603 1265.73,2448.23 r0 top
R44 "RC0603JR-0710KL" 0603 1265.73,2388.23 r180 top
R45 "ERJ-3EKF7501V" 0603 1480.53,1390.91 r180 top
R46 "ERJ-3GEY0R00V" 0603 1327,1765 r0 top
R47 "ERJ-3EKF7501V" 0603 1455.96,1614.91 r90 top
R48 "RC0603FR-073KL" 0603 1457.88,2040.91 r90 top
R49 "ERJ-3GEY0R00V" 0603 1490.96,1519.91 r180 top
R50 "ERJ-3EKF7501V" 0603 1500.26,2618.32 r180 top
R51 "RC0603FR-074K7L" 0603 1547.75,3027.99 r180 top
R52 "RC0603FR-074K7L" 0603 1547.75,2967.99 r180 top
R53 "RC0603FR-074K7L" 0603 1548.28,1054.45 r180 top
R54 "RC0603FR-074K7L" 0603 1548.28,994.45 r180 top
R55 "ERJ-3GEY0R00V" 0603 1516.96,1864.91 r90 top
R56 "ERJ-3GEY0R00V" 0603 1576.53,1359.91 r90 top
R57 "ERJ-3GEY0R00V" 0603 1601.04,2651.34 r270 top
R58 "RC0603FR-074K7L" 0603 1746.78,1055.45 r180 top
R59 "RC0603FR-074K7L" 0603 1746.78,995.45 r180 top
R60 "RC0603FR-074K7L" 0603 1747.75,3027.99 r180 top
R61 "RC0603FR-074K7L" 0603 1747.75,2967.99 r180 top
R62 "ERJ-3EKF7501V" 0603 1752.41,1710.91 r270 top
R63 "RC0603JR-0710KL" 0603 1757.73,2344.45 r270 top
R64 "ERJ-3EKF7501V" 0603 1814.41,1710.91 r270 top
R65 "RC0603FR-074K7L" 0603 1974.73,1679.45 r180 top
R66 "RC0603FR-074K7L" 0603 1974.73,1614.45 r180 top
R67 "RC0603FR-074K7L" 0603 2164.73,1674.45 r180 top
R68 "RC0603FR-074K7L" 0603 2164.73,1614.45 r180 top
R69 "RC0603FR-07130KL" 0603 2366.86,763.86 r0 top
R70 "RC0603FR-07130KL" 0603 2364.73,2247.45 r0 top
R71 "RC0603FR-07130KL" 0603 2368,3677 r0 top
R72 "CRCW0805820RJNEA" 0805_HV 2879.73,4509.45 r90 top
R73 "CRCW0805820RJNEA" 0805_HV 2899.73,2984.45 r90 top
R74 "CRCW0805820RJNEA" 0805_HV 2900.73,1570.45 r90 top
R75 "RC0603JR-0710KL" 0603 2970.73,4429.45 r270 top
R76 "RC0603JR-0710KL" 0603 2983.73,2908.45 r270 top
R77 "RC0603JR-0710KL" 0603 2986.73,1487.45 r270 top
R78 "RC0603JR-0710KL" 0603 3058.73,4324.45 r0 top
R79 "ERJ-3GEY0R00V" 0603 3069.73,1809.45 r180 top
R80 "ERJ-3GEY0R00V" 0603 3069.73,1749.45 r180 top
R81 "CRCW060331K6FKEA" 0603 3071.73,-143.55 r0 top
R82 "CRCW060339R0JNEA" 0603 3071.73,-208.55 r180 top
R83 "CRCW060339R0JNEA" 0603 3071.73,-273.55 r180 top
R84 "RC0603JR-0710KL" 0603 3073.73,2803.45 r0 top
R85 "ERJ-3GEY0R00V" 0603 3074.73,4761.58 r180 top
R86 "ERJ-3GEY0R00V" 0603 3074.73,4696.58 r180 top
R87 "ERJ-3GEY0R00V" 0603 3077.08,3236.32 r180 top
R88 "ERJ-3GEY0R00V" 0603 3077.08,3171.32 r180 top
R89 "RC0603JR-0710KL" 0603 3084.73,1389.45 r0 top
R90 "RC0603FR-0790K9L" 0603 3089.73,409.45 r0 top
R91 "CRCW06035K76FKEA" 0603 3089.73,349.45 r0 top
R92 "CRCW060339R0JNEA" 0603 3089.73,284.45 r180 top
R93 "CRCW060339R0JNEA" 0603 3089.73,224.45 r180 top
R94 "RC1206JR-070RL" 1206 3141.99,2256.45 r0 top
R95 "ERJ-8ENF16R5V" 1206 3141.99,2151.45 r0 top
R96 "RC1206JR-070RL" 1206 3142.12,773.86 r0 top
R97 "ERJ-8ENF16R5V" 1206 3142.12,668.86 r0 top
R98 "RC1206JR-070RL" 1206 3142.99,3684.45 r0 top
R99 "ERJ-8ENF16R5V" 1206 3142.99,3579.45 r0 top
R100 "RC1206JR-070RL" 1206 3150.73,2497.45 r0 top
R101 "RC1206JR-070RL" 1206 3150.86,1014.86 r0 top
R102 "ERJ-8ENF16R5V" 1206 3150.99,2600.45 r0 top
R103 "ERJ-8ENF16R5V" 1206 3151.12,1117.86 r0 top
R104 "RC1206JR-070RL" 1206 3151.73,3925.45 r0 top
R105 "ERJ-8ENF16R5V" 1206 3151.99,4028.45 r0 top
R106 "RT0603DRE0768K1L" 0603 3189.73,194.45 r90 top
R107 "RC0603FR-073K16L" 0603 3204.73,-145.55 r90 top
R108 "CRCW06032K61FKEA" 0603 3204.73,-275.55 r270 top
R109 "RC0603FR-073K01L" 0603 3269.73,-275.55 r270 top
R110 "ERJ-3GEY0R00V" 0603 3488.33,392.32 r180 top
R111 "RC1206JR-070RL" 1206 3610.73,5368.45 r0 top
R112 "RC0603JR-0710KL" 0603 3548.73,3481.45 r90 top
R113 "RC0603JR-0710KL" 0603 3548.73,3036.45 r90 top
R114 "RC0603JR-0710KL" 0603 3548.73,2581.45 r90 top
R115 "RC0603JR-0710KL" 0603 3548.73,2131.45 r90 top
R116 "RC0603JR-0710KL" 0603 3548.73,1681.45 r90 top
R117 "RC0603JR-0710KL" 0603 3746,1219 r90 top
R118 "PWR4412-2SDR0050F" PWR44412-2SD 5673.73,3849.45 r90 top
R119 "PWR4412-2SDR0050F" PWR44412-2SD 5673.73,2535.45 r270 top
R120 "PWR4412-2SDR0050F" PWR44412-2SD 5673.73,1215.45 r270 top
R121 "CRCW1206100KJNEA" 1206 4684.73,4904.45 r180 bottom
R122 "CRCW08051M00JNEA" 0805_HV 4699.73,-75.55 r0 bottom
R123 "CRCW1206100KJNEA" 1206 4514.73,4534.45 r180 bottom
R124 "CRCW1206100KJNEA" 1206 4484.73,4719.45 r0 bottom
R125 "CRCW08051M00JNEA" 0805_HV 4481.73,-75.55 r0 bottom
R126 "CRCW1206100KJNEA" 1206 4424.73,4904.45 r180 bottom
R127 "CRCW08051M00JNEA" 0805_HV 4440.73,-249.54 r90 bottom
R128 "CRCW08051M00JNEA" 0805_HV 4440.73,-458.54 r90 bottom
R129 "CRCW1206100KJNEA" 1206 4244.73,4534.45 r180 bottom
R130 "CRCW08051M00JNEA" 0805_HV 4249.73,-500.55 r0 bottom
R131 "CRCW08051M00JNEA" 0805_HV 4024.73,-500.55 r0 bottom
R132 "ERJ-6GEY0R00V" 0805_HV 3528.73,3020.45 r90 bottom
R133 "ERJ-6GEY0R00V" 0805_HV 3527.73,2117.45 r90 bottom
R134 "ERJ-6GEY0R00V" 0805_HV 3527.73,1222.45 r90 bottom
R135 "ERJ-6GEY0R00V" 0805_HV 3464.73,483.45 r90 bottom
R136 "CRCW08051R33FKEA" 0805_HV 2912.73,4237.45 r0 bottom
R137 "CRCW08051R33FKEA" 0805_HV 2911.86,1324.86 r0 bottom
R138 "CRCW08051R33FKEA" 0805_HV 2911.73,2800.45 r0 bottom
R139 "RC0603FR-07100RL" 0603 2249.73,2612.45 r180 bottom
R140 "RC0603FR-07100RL" 0603 2248.73,2424.45 r180 bottom
R141 "RC0603FR-07100RL" 0603 2246.73,1129.45 r180 bottom
R142 "RC0603FR-07100RL" 0603 2246.73,934.45 r180 bottom
R143 "RC0603FR-07100RL" 0603 2230.73,3848.99 r180 bottom
R144 "RC0603FR-07100RL" 0603 2229.73,4036.45 r180 bottom
R145 "ERJ-3GEY0R00V" 0603 1227.73,1363.99 r270 bottom
R146 "PHT0603Y1002BGT200" 0603 1129.73,1393.99 r0 bottom
R147 "RG1608P-822-B-T5" 0603 1128.73,1331.99 r180 bottom
R148 "PHT0603Y1002BGT200" 0603 969.73,1539.45 r270 bottom
R149 "ERJ-3GEY0R00V" 0603 950.73,1194.45 r270 bottom
R150 "PHT0603Y1002BGT200" 0603 901.76,1540.45 r270 bottom
R151 "CRCW06035M11FKEA" 0603 1095.73,1366.73 r270 top
R152 "ERJ-3GEY0R00V" 0603 885,1195 r270 bottom
R153 "PHT0603Y1002BGT200" 0603 834.73,1539.45 r270 bottom
R154 "RC0603JR-0710KL" 0603 822.76,1194.45 r90 bottom
R155 "PHT0603Y1002BGT200" 0603 683.76,1306.45 r180 bottom
R156 "RG1608P-123-B-T5" 0603 683.76,1244.45 r0 bottom
R157 "RG1608P-201-B-T5" 0603 587.76,1275.45 r270 bottom
R158 "ERJ-3GEY0R00V" 0603 490,3403 r90 bottom
R159 "ERJ-3GEY0R00V" 0603 532,3617 r90 top
R160 "ERJ-3GEY0R00V" 0603 1116.73,3299.82 r0 bottom
R161 "ERJ-3GEY0R00V" 0603 1152,3507 r0 bottom
R162 "ERJ-3GEY0R00V" 0603 1190,1833 r180 top
R163 "ERJ-3GEY0R00V" 0603 1044,2001 r180 bottom
R164 "ERJ-3GEY0R00V" 0603 2464.73,3434 r90 bottom
R165 "ERJ-3GEY0R00V" 0603 2462,1348 r270 bottom
R166 "ERJ-3GEY0R00V" 0603 2462,1999 r90 bottom
R167 "RC0603JR-071KL" 0603 1759,2547 r90 top
R168 "ERJ-3GEY0R00V" 0603 646,2773 r90 top
R169 "ERJ-3GEY0R00V" 0603 1287,2775 r90 top
R170 "ERJ-3GEY0R00V" 0603 1458,1765 r0 top
TP1 "5000" Keystone5000 613.38,133.61 r90 top
TP2 "5000" Keystone5000 949.73,1059.45 r90 top
TP3 "5000" Keystone5000 978.73,291.45 r90 top
TP4 "5000" Keystone5000 978.73,696.45 r90 top
TP5 "5000" Keystone5000 2259.73,4799.45 r0 top
TP6 "5000" Keystone5000 2259.73,4654.45 r0 top
TP7 "5000" Keystone5000 3334.73,284.45 r0 top
TP8 "TESTPOINT" PAD_100mil-40milhole 5674.73,3084.45 r0 top
TP9 "TESTPOINT" PAD_100mil-40milhole 5674.73,1749.45 r90 top
TP10 "TESTPOINT" PAD_100mil-40milhole 5989.73,4249.45 r0 top
U1 "OPA320AIDBVR" DBV0005A_N 418.73,1499.4 r270 top
U2 "TLC372QDRG4" D0008A_N 565.51,3397.34 r90 top
U3 "TLV1117-33IDCYR" DCY0003A_N 671.73,588.45 r0 top
U4 "REF2033AIDDCT" DDC0005A_N 665.38,350.61 r180 top
U5 "OPA320AIDBVR" DBV0005A_N 824.73,2789.45 r0 top
U6 "TLC372QDRG4" D0008A_N 1149.21,3401.76 r90 top
U7 "TLC372QDRG4" D0008A_N 1267.88,1975.91 r180 top
U8 "SN74LVC1G10DBVR" DBV0006A_N 1290,2265 r180 top
U9 "OPA320AIDBVR" DBV0005A_N 1485.06,2779.12 r0 top
U10 "OPA320AIDBVR" DBV0005A_N 1504.73,1218.91 r0 top
U11 "OPA320AIDBVR" DBV0005A_N 1625.96,1634.91 r270 top
U12 "AMC1311DWVR" DWV0008A 2671.73,-243.55 r180 top
U13 "AMC1301DWVR" DWV0008A 2674.73,4726.58 r180 top
U14 "AMC1301DWVR" DWV0008A 2674.73,1779.45 r180 top
U15 "AMC1311DWVR" DWV0008A 2674.73,254.45 r180 top
U16 "AMC1301DWVR" DWV0008A 2677.08,3201.32 r180 top
U17 "UCC21520DW" DW0016A_N 2672.99,2369.45 r0 top
U18 "UCC21520DW" DW0016A_N 2673.12,886.86 r0 top
U19 "UCC21520DW" DW0016A_N 2673.99,3797.45 r0 top
U20 "TL431BQDBZR" DBZ0003A_N 3074.73,4424.45 r0 top
U21 "TL431BQDBZR" DBZ0003A_N 3088.73,2903.45 r0 top
U22 "TL431BQDBZR" DBZ0003A_N 3092.73,1488.45 r0 top
U23 "TLV70433DBVT" DBV0005A_N 3457.33,110.32 r270 top
U24 "MG1250H-XN2MM" IXYS_E2 4481.73,2347.45 r270 bottom
U25 "TLC372QDRG4" D0008A_N 910.76,1365.45 r0 bottom
ZZ1 "This Assembly Note is for PCB labels only" AssemblyNoteLabel 64.73,6629.45 r0 top
ZZ2 "These assemblies are ESD sensitive, ESD precautions shall be observed." AssemblyNote 1419.73,9185.45 r0 top
ZZ3 "These assemblies must be clean and free from flux and all contaminants. Use of no clean flux is not acceptable." AssemblyNote 1419.73,9100.45 r0 top
ZZ4 "These assemblies must comply with workmanship standards IPC-A-610 Class 2, unless otherwise specified." AssemblyNote 1419.73,9025.45 r0 top

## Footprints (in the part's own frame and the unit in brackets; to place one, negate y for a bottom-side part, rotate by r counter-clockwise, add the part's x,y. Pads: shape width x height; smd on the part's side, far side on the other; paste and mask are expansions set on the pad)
0402 [mm] "0402 from SM-752 data"
  rect 0.8x0.6 smd: 1(-0.6,0) 2(0.6,0)
  silkscreen extent -1.22,-0.52 1.22,0.52, body extent -0.55,-0.3 0.55,0.3, height 0.6
0603 [mm] "0603 from SM-752 data"
  rect 1x0.95 smd: 1(-0.8,0) 2(0.8,0)
  silkscreen extent -1.52,-0.69 1.52,0.69, body extent -0.87,-0.47 0.87,0.47, height 1
0805_HV [mil] "0805 with 30mil clearance between pads"
  rect 50x63 smd: 1(-40,0) 2(40,0)
  silkscreen extent -74,-40 74,40, body extent -43,-29 43,29, height 57
1206 [mm] "1206 from SM-752 data"
  rect 1.3x1.85 smd: 1(-1.45,0) 2(1.45,0)
  silkscreen extent -2.4,-1.21 2.4,1.21, body extent -1.7,-0.9 1.7,0.9, height 1.35
1210_280 [mm] "SMD, 2-Leads, Body 3.6x2.8mm, Height 2.8mm"
  rect 1.1x2.2 smd: 1(-1.65,0) 2(1.65,0)
  silkscreen extent -0.84,-1.4 0.84,1.4, body extent -1.8,-1.4 1.8,1.4, height 2.8
AssemblyNote [mil] "Assembly Note"
AssemblyNoteLabel [mil] "Assembly Note for PCB Labels"
B32774_3150x1800x2750 [mm] "TH, 2-Leads, Body 31.5x18mm, Pin Spacing 27.5mm"
  round 1.6 hole 1.1: 1(-13.75,0) 2(13.75,0)
  silkscreen extent -15.75,-9 15.75,9, body extent -15.75,-9 15.75,9, height 27.5
D0008A_N [mm] "SOIC, 8-Leads, Body 4.9x3.9mm, Pitch 1.27mm, IPC Medium Density"
  oval 1.45x0.6 smd: 1(-2.725,1.905) 2(-2.725,0.635) 3(-2.725,-0.635) 4(-2.725,-1.905) 5(2.725,-1.905) 6(2.725,-0.635) 7(2.725,0.635) 8(2.725,1.905)
  silkscreen extent -3.3,-2.5 0.9,2.5, body extent -3,-2.45 3,2.45, height 1.63
DBV0005A_N [mm] "SOT23, 5-Leads, Body 2.9x1.6mm, Pitch 0.95mm, Lead Span 2.8mm, IPC Medium Density"
  rrect17% 1x0.6 smd: 1(-1.375,0.95) 2(-1.375,0) 3(-1.375,-0.95) 4(1.375,-0.95) 5(1.375,0.95)
  silkscreen extent -1.63,-1.55 0.38,1.55, body extent -1.42,-1.46 1.42,1.46, height 1.09
DBV0006A_N [mm] "SOT23, 6-Leads, Body 2.9x1.6mm, Pitch 0.95mm, Lead Span 2.8mm, IPC Medium Density"
  rrect17% 1x0.6 smd: 1(-1.375,0.95) 2(-1.375,0) 3(-1.375,-0.95) 4(1.375,-0.95) 5(1.375,0) 6(1.375,0.95)
  silkscreen extent -1.68,-1.55 0.5,1.55, body extent -1.42,-1.46 1.42,1.46, height 1.12
DBZ0003A_N [mm] "SOT23, 3-Leads, Body 2.9x1.3mm, Pitch 0.95mm, Lead Span 2.4mm, IPC Medium Density"
  rrect17% 1x0.6 smd: 1(-1.2,0.95) 2(-1.2,-0.95) 3(1.2,0)
  silkscreen extent -1.65,-1.5 0.7,1.5, body extent -1.26,-1.46 1.26,1.46, height 0.98
DCY0003A_N [mm] "SOT223/SC73, 4-Leads, Body 6.5x3.5mm, Pitch 2.3mm, Lead Span 7mm, IPC Medium Density"
  rrect11% 1.75x0.9 smd: 1(-3.125,2.3) 2(-3.125,0) 3(-3.125,-2.3)
  rrect6% 1.75x3.2 smd: 4(3.125,0)
  silkscreen extent -3.02,-3.35 1.4,3.47, body extent -3.51,-3.25 3.51,3.25, height 1.8
DDC0005A_N [mm]
  rrect17% 1x0.6 smd: 1(-1.375,0.95) 2(-1.375,0) 3(-1.375,-0.95) 4(1.375,-0.95) 5(1.375,0.95)
  silkscreen extent -1.75,-1.52 0.88,1.53, body extent -1.41,-1.45 1.41,1.45, height 1.1
DW0016A_N [mm] "SOIC, 16-Leads, Body 10.3x7.5mm, Pitch 1.27mm, IPC Medium Density"
  oval 1.9x0.6 smd: 1(-4.75,4.445) 2(-4.75,3.175) 3(-4.75,1.905) 4(-4.75,0.635) 5(-4.75,-0.635) 6(-4.75,-1.905) 7(-4.75,-3.175) 8(-4.75,-4.445) 9(4.75,-4.445) 10(4.75,-3.175) 11(4.75,-1.905) 12(4.75,-0.635) 13(4.75,0.635) 14(4.75,1.905) 15(4.75,3.175) 16(4.75,4.445)
  silkscreen extent -5.6,-5.25 3,5.25, body extent -5.14,-5.13 5.14,5.13, height 2.54
DWV0008A [mm] "SOIC, 8-Leads, Body 5.95x7.6mm (max), Pitch 1.27mm"
  rrect17% 1.8x0.6 smd: 1(-5.45,1.905) 2(-5.45,0.635) 3(-5.45,-0.635) 4(-5.45,-1.905) 5(5.45,-1.905) 6(5.45,-0.635) 7(5.45,0.635) 8(5.45,1.905)
  silkscreen extent -6.25,-2.95 2.98,2.95, body extent -5.77,-2.92 5.77,2.93, height 2.67
ESD_Overlay_Medium [mil]
  silkscreen extent -127,-109 125,110
FCC_disclaimer [mil]
Fiducial10-20 [mm]
  round 1 smd mask+0.5: 1(0,0)
  Top Layer keep-out circle w1.178: c0,0 r0.5
IEC_Caution_Medium [mil]
  silkscreen extent -217,-182 217,193
IEC_HighVoltage_medium [mil]
  silkscreen extent -217,-176 217,200
IEC_HotSurface_Medium [mil]
  silkscreen extent -217,-188 217,188
IXYS_E2 [mm] "Six-Pack Trench IGBT, Body 107.5x45mm"
  round 2.2 hole 1.7: 1(-30.48,20.95) 2(-26.67,20.95) 3(-19.05,20.95) 4(-15.24,20.95) 5(-7.62,20.95) 6(-3.81,20.95) 7(3.81,20.95) 8(7.62,20.95) 9(15.24,20.95) 10(19.05,20.95) 11(26.67,20.95) 12(30.48,20.95) 13(39.6,11.43) 14(39.6,7.62) 15(39.6,-7.62) 16(39.6,-11.43) 17(30.48,-20.95) 18(26.67,-20.95) 19(15.24,-20.95) 20(11.43,-20.95) 21(-3.81,-20.95) 22(-7.62,-20.95) 23(-22.86,-20.95) 24(-26.67,-20.95) 25(-39.6,-11.43) 26(-39.6,-7.62) 27(-39.6,7.62) 28(-39.6,11.43)
  round 2.5 hole 2.5 unplated mask+0: MH1(-46.5,16) MH2(-46.5,-16) MH4(46.5,16) MH5(46.5,-16)
  round 6 hole 6 unplated paste+0 mask+0: MH3(-46.5,0) MH6(46.5,0)
  silkscreen extent -53.9,-22.6 53.9,23.1, body extent -53.9,-22.6 53.9,22.6, height 17.5
Keystone5000 [mil] "For Keystone 500x miniature loop terminals"
  round 80 hole 40: 1(0,0)
  silkscreen extent -58,-58 58,58, body extent -49,-49 49,49, height 182
Keystone_1902C [mil] "Hex Standoff, 4-40 threaded, nylon"
  round 1 on Mech4: 0(0,0)
  body extent -145,-126 146,126, height 501
Label_650x200 [mil] "Thermal Transfer Label"
  round 1 on Mech13: 0(0,0)
  silkscreen extent -325,-100 325,100, body extent -325,-100 325,100, height 1
MH3.2_H5_W6_KO8_STARHEAD [mil]
  round 20 / inner round 142 / far side round 20 hole 128 unplated mask+65: 1(0,0)
  Keep-Out Layer region: 160.49,0 158.52,25.11 152.64,49.6 143,72.86 129.84,94.34 113.49,113.49 94.34,129.84 72.86,143 49.6,152.64 25.11,158.52 0,160.49 -25.11,158.52 -49.6,152.64 -72.86,143 -94.34,129.84 -113.49,113.49 -129.84,94.34 -143,72.86 -152.64,49.6 -158.52,25.11 -160.49,0 -158.52,-25.11 -152.64,-49.6 -143,-72.86 -129.84,-94.34 -113.49,-113.49 -94.34,-129.84 -72.86,-143 -49.6,-152.64 -25.11,-158.52 0,-160.49 25.11,-158.52 49.6,-152.64 72.86,-143 94.34,-129.84 113.49,-113.49 129.84,-94.34 143,-72.86 152.64,-49.6 158.52,-25.11
  silkscreen extent -120,-120 120,120
MicroSMP [mm] "SMD, 2-Leads, Body 2.2x1.3mm"
  rect 2x1.1 smd: 1(-0.65,0)
  rect 0.8x0.8 smd: 2(1.25,0)
  silkscreen extent -2.2,-1 1.6,1, body extent -1.15,-0.7 1.15,0.7, height 0.75
Mill-Max_800-10-002-10-001000 [mm] "Mill-Max"
  rect 1.5x1.5 hole 0.85: 1(-1.27,0)
  round 1.5 hole 0.85: 2(1.27,0)
  silkscreen extent -2.54,-1.27 2.54,1.78, body extent -2.54,-1.27 2.54,1.27, height 8.13
PAD_100mil-40milhole [mil]
  round 100 hole 40: 1(0,0)
Pb-Free_Overlay_Small [mil]
  silkscreen extent -46,-46 46,46
PHOENIX_1902547#1 [mm] "CONN, PCB TERMINAL BLOCK, 9.52 MM PITCH, 2POS, TH"
  rect 1.8x1.8 / inner round 1.8 / far side rect 1.8x1.8 hole 1.3: 1(-4.76,3.1)
  round 1.8 hole 1.3: 2(4.76,3.1)
  silkscreen extent -10.38,-8 9.52,8, body extent -9.53,-8 10.09,8, height 21.5
PHOENIX_1902547#2 [mm] "CONN, PCB TERMINAL BLOCK, 9.52 MM PITCH, 3POS, TH"
  rect 1.8x1.8 / inner round 1.8 / far side rect 1.8x1.8 hole 1.3: 1(-9.52,3.1)
  round 1.8 hole 1.3: 2(0,3.1) 3(9.52,3.1)
  silkscreen extent -15.14,-8 14.28,8, body extent -14.27,-8 14.86,8, height 21.5
PWR44412-2SD [mm] "TH, 2-Leads, Pin Spacing 20.32mm"
  round 2.2 hole 1.7: 1(-10.16,0) 2(10.16,0)
  silkscreen extent -10.66,-2.4 10.67,2.4, body extent -10.66,-2.4 10.67,2.4, height 25.4
SMA [mm] "Molded Diode, 2-Leads, Body 4.3x2.6mm, IPC Medium Density, based on OnSemi component dimensions and land pattern"
  rect 2x2 smd: 1(-2,0) 2(2,0)
  silkscreen extent -3.66,-1.57 2.79,1.57, body extent -2.6,-1.3 2.6,1.3, height 2.42
SMB [mil] "Molded Diode, 2-Leads, Body 5.4x3.6mm, IPC Medium Density, based on OnSemi component dimensions"
  rect 85x107.99 smd: 1(-87.01,0) 2(87.01,0)
  silkscreen extent -155,-82 125,82, body extent -106,-71 106,71, height 91
TEC_282834-2 [mm] "TEC"
  rect 1.6x1.6 hole 1.1: 1(-1.27,0)
  round 1.6 hole 1.1: 2(1.27,0)
  silkscreen extent -3.66,-3.4 2.9,3.4, body extent -2.77,-3.25 2.77,3.25, height 10.01
TSW-110-07-G-D [mm] "Samtec 100mil, 2x10, 230 mil above insulator"
  rrect6% 1.65x1.65 hole 1.016: 1(-11.43,-1.27)
  round 1.65 hole 1.016: 2(-11.43,1.27) 3(-8.89,-1.27) 4(-8.89,1.27) 5(-6.35,-1.27) 6(-6.35,1.27) 7(-3.81,-1.27) 8(-3.81,1.27) 9(-1.27,-1.27) 10(-1.27,1.27) 11(1.27,-1.27) 12(1.27,1.27) 13(3.81,-1.27) 14(3.81,1.27) 15(6.35,-1.27) 16(6.35,1.27) 17(8.89,-1.27) 18(8.89,1.27) 19(11.43,-1.27) 20(11.43,1.27)
  silkscreen extent -12.7,-3.22 12.7,2.54, body extent -12.7,-2.54 12.7,2.54, height 8.38

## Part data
C1 C10 C55 C56 C57 C58 C59 C60 C61 C62 C71 C73 C75 C80 C85 C86 C95 C96: "CAP, CERM, 4.7 µF, 50 V, +/- 10%, X5R, 0805"
C2 C3 C7 C8 C9 C11 C13 C14 C15 C20 C21 C22 C23 C25 C26 C30 C31 C32 C34 C35 C36 C37 C38 C44 C47 C48 C49 C52 C63 C64 C65 C66 C67 C68 C69 C70 C72 C74 C76 C82 C87 C89 C90 C91 C94 C97 C108: "CAP, CERM, 0.1 µF, 50 V, +/- 10%, X7R, 0603"
C4 C6 C16 C18 C33 C40 C41 C42 C46 C51 C81 C83 C84 C88 C92: "CAP, CERM, 0.01 µF, 16 V, +/- 10%, X7R, 0603"
C5 C93: "CAP, CERM, 10 µF, 50 V, +/- 10%, X5R, 1210"
C12 C17 C19: "CAP, CERM, 1500 pF, 100 V, +/- 5%, X7R, 0603"
C24: "CAP, CERM, 22 µF, 25 V, +/- 20%, X5R, 0805"
C27 C28 C29 C39 C43 C45 C50 C53 C54: "CAP, CERM, 180 pF, 50 V, +/- 5%, C0G/NP0, 0603"
C77 C78 C79: "CAP, CERM, 0.47 µF, 50 V, +/- 10%, X5R, 0603"
C98 C99 C100: "CAP, CERM, 2.2 µF, 50 V, +/- 10%, X7R, 0805"
C101 C102 C103 C104 C105 C106: "CAP, CERM, 10 pF, 50 V, +/- 5%, C0G/NP0, 0603"
C107 C109 C110: "CAP, CERM, 820 pF, 50 V, +/- 10%, X7R, 0603"
C111 C112: "CAP, Film, 3 µF, 1300 V, +/- 10%, 0.016 ohm, TH"
C113 C114 C115: "CAP, CERM, 2200 pF, 16 V, +/- 10%, X7R, 0402"
Caution: library part IEC_Caution, "IEC 61010-1 Caution Warning"
"CAUTION HOT SURFACE": library part IEC_HotSurface, "IEC 61010-1 Hot Surface Warning"
D1 D8: "Diode, Schottky, 100 V, 1 A, SMA"
D3 D4 D5 D6 D7 D9: library part MSS1P3L-M3/89A, "Diode, Schottky, 30 V, 2 A, AEC-Q101, MicroSMP"
D10 D11: "Diode, Zener, 200 V, 550 mW, SMB"
D12 D13 D14: "Diode, Ultrafast, 1300 V, 1 A, SMA"
FID1 FID2 FID3 FID4 FID5 FID6: "Fiducial mark.  There is nothing to buy or mount."
H1 H2 H3 H4: library part "MH 3_0.5MM", "Mountin hole, NPTH Drill 3.2mm"
H5 H6 H7 H8: "Standoff, Hex, 0.5\"L #4-40 Nylon"
J1 J4: "Terminal Block, 2x1, 2.54mm, TH"
J2 J3: "Header, 100mil, 10x2, Gold, TH"
J5 J6 J7: "Header, 100mil, 2x1, TH"
J13: library part 691133810002, "Horizontal Cable Entry with Pressure Clamp, Serie 1338 - 10.00 mm"
J14: library part 691131810003, "Horizontal Cable Entry with Pressure Clamp, Serie 1318 - 10.00 mm"
LBL1: library part THT-14-423-10, "Thermal Transfer Printable Labels, 0.650\" W x 0.200\" H - 10,000 per roll"
Logo2: library part Pb-Free
Logo3: library part FCC_disclaimer, "FCC_disclaimer"
LOGO4 LOGO6 LOGO7: library part IEC_HighVoltage, "IEC 61010-1 High Voltage Warning"
Pb_Free: library part ESD_Susceptible, "ESD Susceptible Symbol"
R1 R7 R132 R133 R134 R135: "RES, 0, 5%, 0.125 W, 0805"
R2 R18 R24 R25 R27 R39 R40 R41 R45 R47 R50 R62 R64: "RES, 7.50 k, 1%, 0.1 W, 0603"
R3 R42: "RES, 15.0 k, 1%, 0.1 W, 0603"
R4 R5 R9 R10 R26 R28 R29 R30 R51 R52 R53 R54 R58 R59 R60 R61 R65 R66 R67 R68: "RES, 4.70 k, 1%, 0.1 W, 0603"
R6 R8 R14 R15 R22 R31 R33 R38 R43 R46 R49 R55 R56 R57 R79 R80 R85 R86 R87 R88 R110 R145 R149 R152 R158 R159 R160 R161 R162 R163 R164 R165 R166 R168 R169 R170: "RES, 0, 5%, 0.1 W, 0603"
R11 R44 R63 R75 R76 R77 R78 R84 R89 R112 R113 R114 R115 R116 R117 R154: "RES, 10 k, 5%, 0.1 W, 0603"
R12 R13 R16 R17 R19 R139 R140 R141 R142 R143 R144: "RES, 100, 1%, 0.1 W, 0603"
R20 R35 R48: "RES, 3.00 k, 1%, 0.1 W, 0603"
R21 R32 R34: "RES, 1.50 k, 1%, 0.1 W, 0603"
R23 R36 R37: "RES, 7.15 k, 0.1%, 0.1 W, 0603"
R69 R70 R71: "RES, 130 k, 1%, 0.1 W, 0603"
R72 R73 R74: "RES, 820, 5%, 0.125 W, 0805"
R81: "RES, 31.6 k, 1%, 0.1 W, 0603"
R82 R83 R92 R93: "RES, 39, 5%, 0.1 W, 0603"
R90: "RES, 90.9 k, 1%, 0.1 W, 0603"
R91: "RES, 5.76 k, 1%, 0.1 W, 0603"
R94 R96 R98 R100 R101 R104 R111: "RES, 0, 5%, 0.25 W, 1206"
R95 R97 R99 R102 R103 R105: "RES, 16.5, 1%, 0.25 W, 1206"
R106: "RES, 68.1 k, 0.5%, 0.1 W, 0603"
R107: "RES, 3.16 k, 1%, 0.1 W, 0603"
R108: "RES, 2.61 k, 1%, 0.1 W, 0603"
R109: "RES, 3.01 k, 1%, 0.1 W, 0603"
R118 R119 R120: "RES, 0.005, 1%, 5 W, 20.32x4.80mm"
R121 R123 R124 R126 R129: "RES, 100 k, 5%, 0.25 W, 1206"
R122 R125 R127 R128 R130 R131: "RES, 1.0 M, 5%, 0.125 W, 0805"
R136 R137 R138: "RES, 1.33, 1%, 0.125 W, 0805"
R146 R148 R150 R153 R155: "RES, 10.0 k, 0.1%, 0.0375 W, 0603"
R147: "RES, 8.20 k, 0.1%, 0.1 W, 0603"
R151: "RES, 5.11 M, 1%, 0.1 W, 0603"
R156: "RES, 12.0 k, 0.1%, 0.1 W, 0603"
R157: "RES, 200, 0.1%, 0.1 W, 0603"
R167: "RES, 1.0 k, 5%, 0.1 W, 0603"
TP1 TP2 TP3 TP4 TP5 TP6 TP7: "Test Point, Miniature, Red, TH"
TP8 TP9 TP10: library part PAD_100mil-40milhole, "100mil pad, 40mil hole"
U1 U5 U9 U10 U11: "Precision, 20 MHz, 0.9 pA Ib, RRIO, CMOS Operational Amplifier, 1.8 to 5.5 V, -40 to 125 degC, 5-pin SOT23 (DBV0005A), Green (RoHS & no Sb/Br)"
U2 U6 U7 U25: library part TLC372QDR, "LinCMOS Dual Differential Comparators, D0008A"
U3: library part TLV1117-33IDCY, "FIXED LOW-DROPOUT VOLTAGE REGULATOR, DCY0003A"
U4: library part REF2033AIDDCR, "Low-Drift, Low-Power, Dual-Output, VREF and VREF / 2 Voltage References, DDC0005A"
U8: "Single 3-Input Positive-NAND Gate, DBV0006A"
U12 U15: library part CMP-0013503-2, "Precision, 2-V Input, Reinforced Isolated Amplifier, DWV0008A (SOIC-8)"
U13 U14 U16: "200 kHz, Fully-Differential Isolation Amplifier, DWV0008A"
U17 U18 U19: "4A/6A, 5KVrms Dual Isolated-channel Universal Gate Driver, DW0016A"
U20 U21 U22: library part TL431BQDBZT, "Adjustable Precision Shunt Regulator, 34 ppm / degC, 100 mA, -40 to 125 degC, 3-pin SOT-23 (DBZ), Green (RoHS & no Sb/Br)"
U23: library part TLV70433DBVR, "Single Output LDO, 150 mA, Fixed 3.3 V Output, 2.5 to 24 V Input, with Ultra-Low IQ, 5-pin SOT-23 (DBV), -40 to 125 degC, Green (RoHS & no Sb/Br)"
U24: library part "MWI 50-12T7T", "IGBT MOD 1200V 50A PKG H CRCT:X"
ZZ1: library part AssemblyNoteLabel
ZZ2 ZZ3 ZZ4: library part AssemblyNote

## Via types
v1: diameter 32, hole 16, Top Layer to Bottom Layer, 258 vias
v2: diameter 24, hole 12, Top Layer to Bottom Layer, 7 vias

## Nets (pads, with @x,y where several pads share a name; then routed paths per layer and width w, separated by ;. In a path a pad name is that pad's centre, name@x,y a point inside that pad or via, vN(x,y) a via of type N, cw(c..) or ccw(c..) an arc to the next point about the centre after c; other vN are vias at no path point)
1V65_REF: C3.2 C8.1 C26.2 C30.1 C37.2 C38.2 C52.2 J2.6 R2.1 R25.1 R40.1 R41.1 R62.1 TP3.1 U4.1 | length 7212.5
  Top Layer w15: C30.1@786.92,294.11 C30.1@790.38,294.11
  Top Layer w20: C3.2@188.73,1550.9 188.73,1597.91 213.73,1622.91 v1(358.73,1622.91) ; C3.2@192.23,1554.4 R2.1@252.23,1554.4 ; J2.6@241.73,2629.45 241.73,2637.23 C8.1@338.5,2734 338.5,2767.5 357,2786 v1(371,2786) ; v1(604.23,2914.95) 654.73,2914.95 656.24,2913.45 R25.1@719.24,2913.45 ; U4.1@719.51,313.21 767.83,313.21 C30.1@786.92,294.11 ; v1(1260.07,2905.12) 1261.57,2903.63 C37.2@1313.06,2903.63 1313.57,2903.12 R40.1@1380.57,2903.12 ; v1(1264.73,1120.91) 1266.23,1122.4 C38.2@1324.73,1122.4 1326.23,1120.91 R41.1@1388.24,1120.91 ; R62.1@1752.41,1742.4 1752.41,1805.4 C52.2@1752.92,1805.91 1752.92,1857.4 v1(1754.41,1858.9)
  Top Layer w30: C30.1@790.38,294.11 976.07,294.11 TP3.1@978.73,291.45
  Bottom Layer w20: v1(371,2786) 488,2786 504,2770 ; v1(1260.07,2905.12) 1250.24,2914.95 v1(604.23,2914.95) 604.23,2842.23 532,2770 ; v1(1754.41,1858.9) 1754.41,1479.45 1395.87,1120.91 v1(1264.73,1120.91) 1264.73,821.73 978.73,535.73 TP3.1@978.73,291.45 711.55,291.45 358.73,644.27 v1(358.73,1622.91) 358.73,2596.73 504,2742 ; 504,2742 504,2770 ; 504,2742 532,2770 ; 504,2770 532,2770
